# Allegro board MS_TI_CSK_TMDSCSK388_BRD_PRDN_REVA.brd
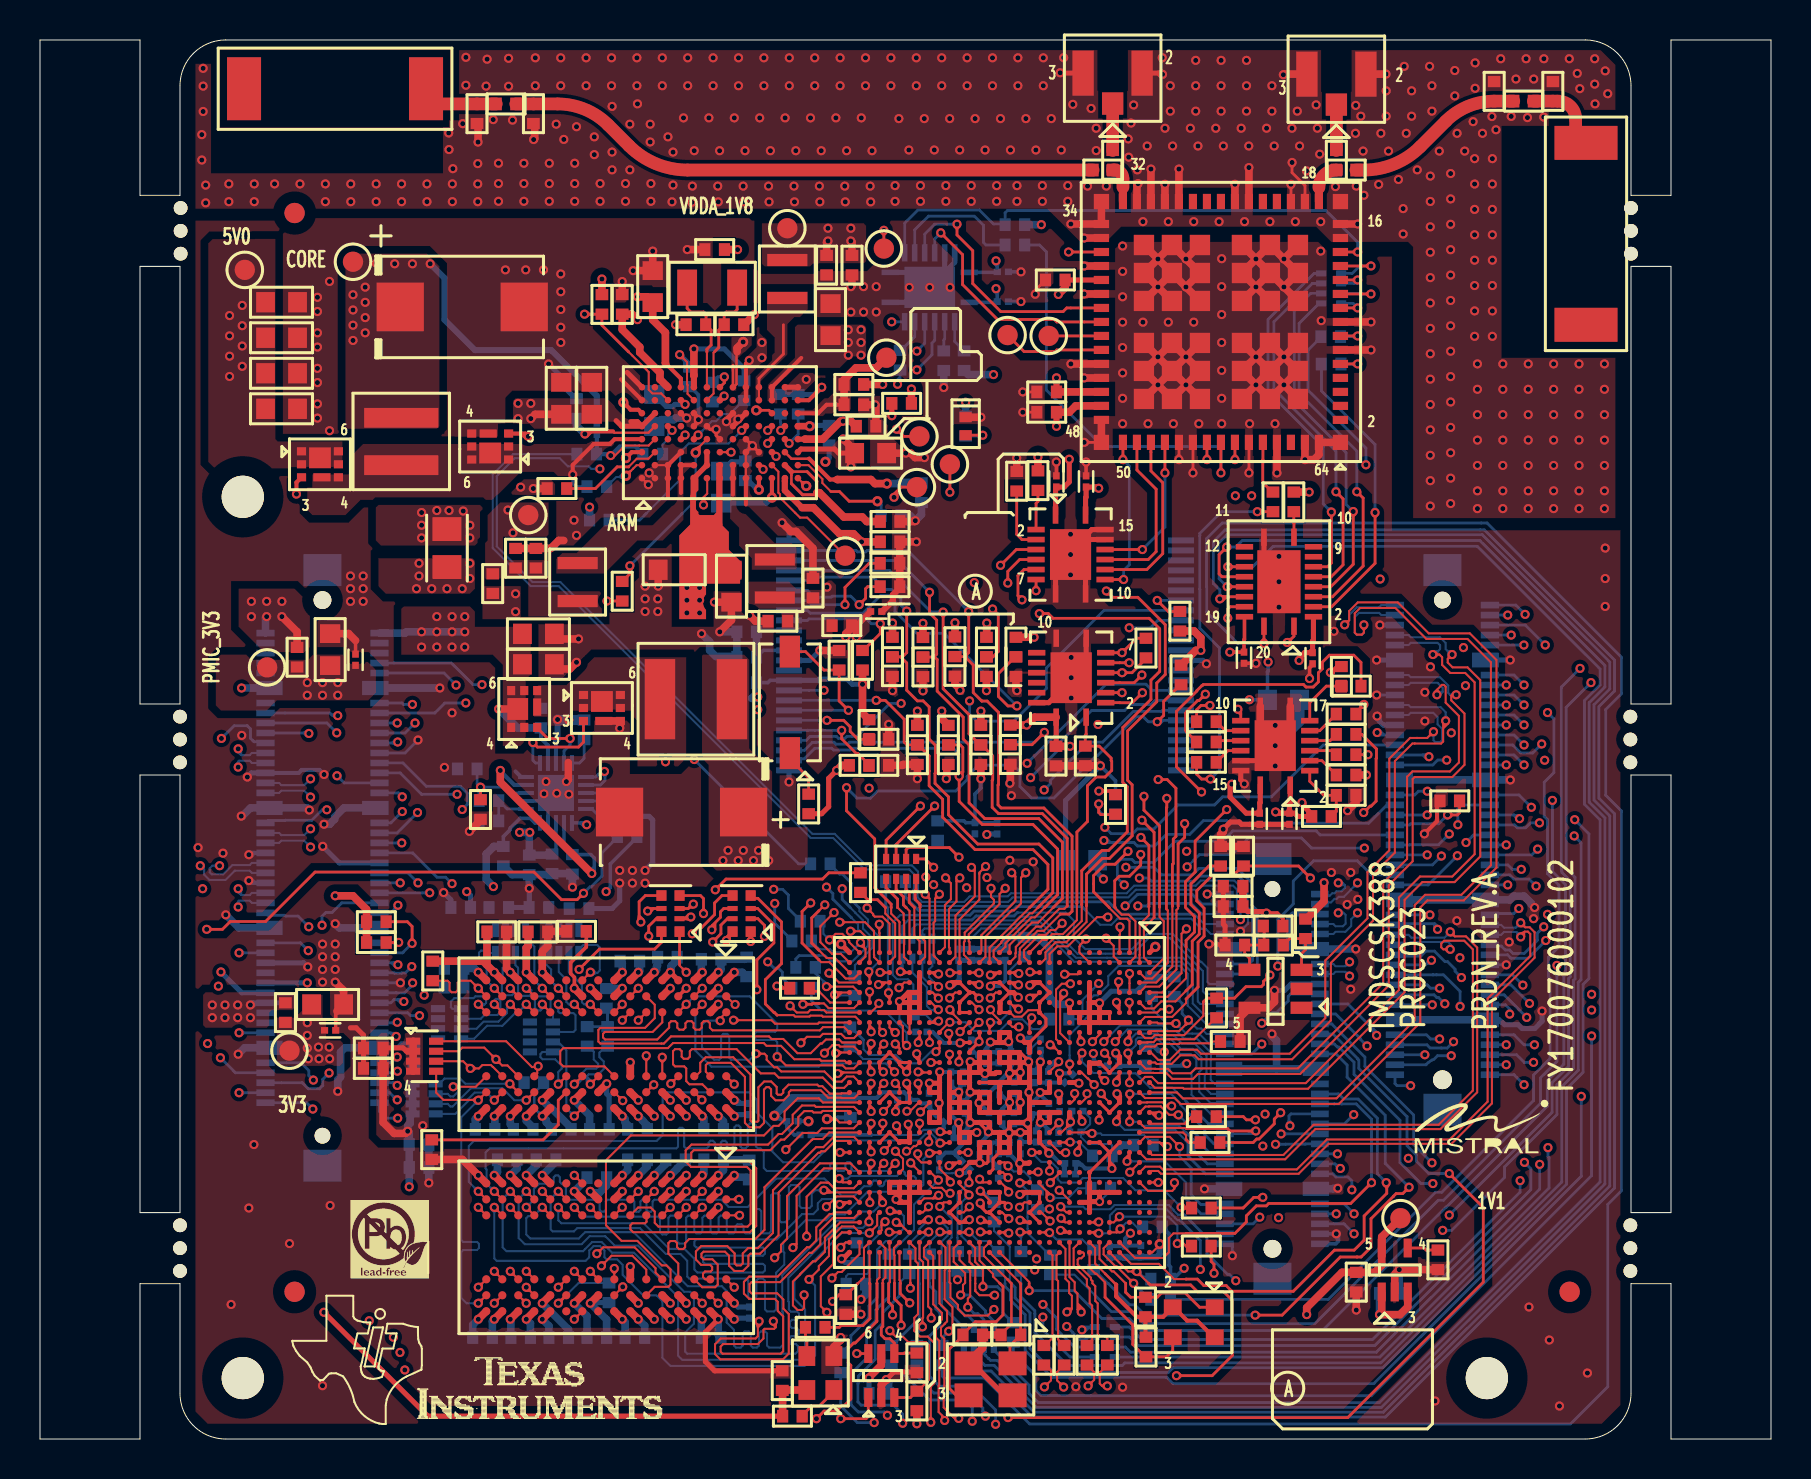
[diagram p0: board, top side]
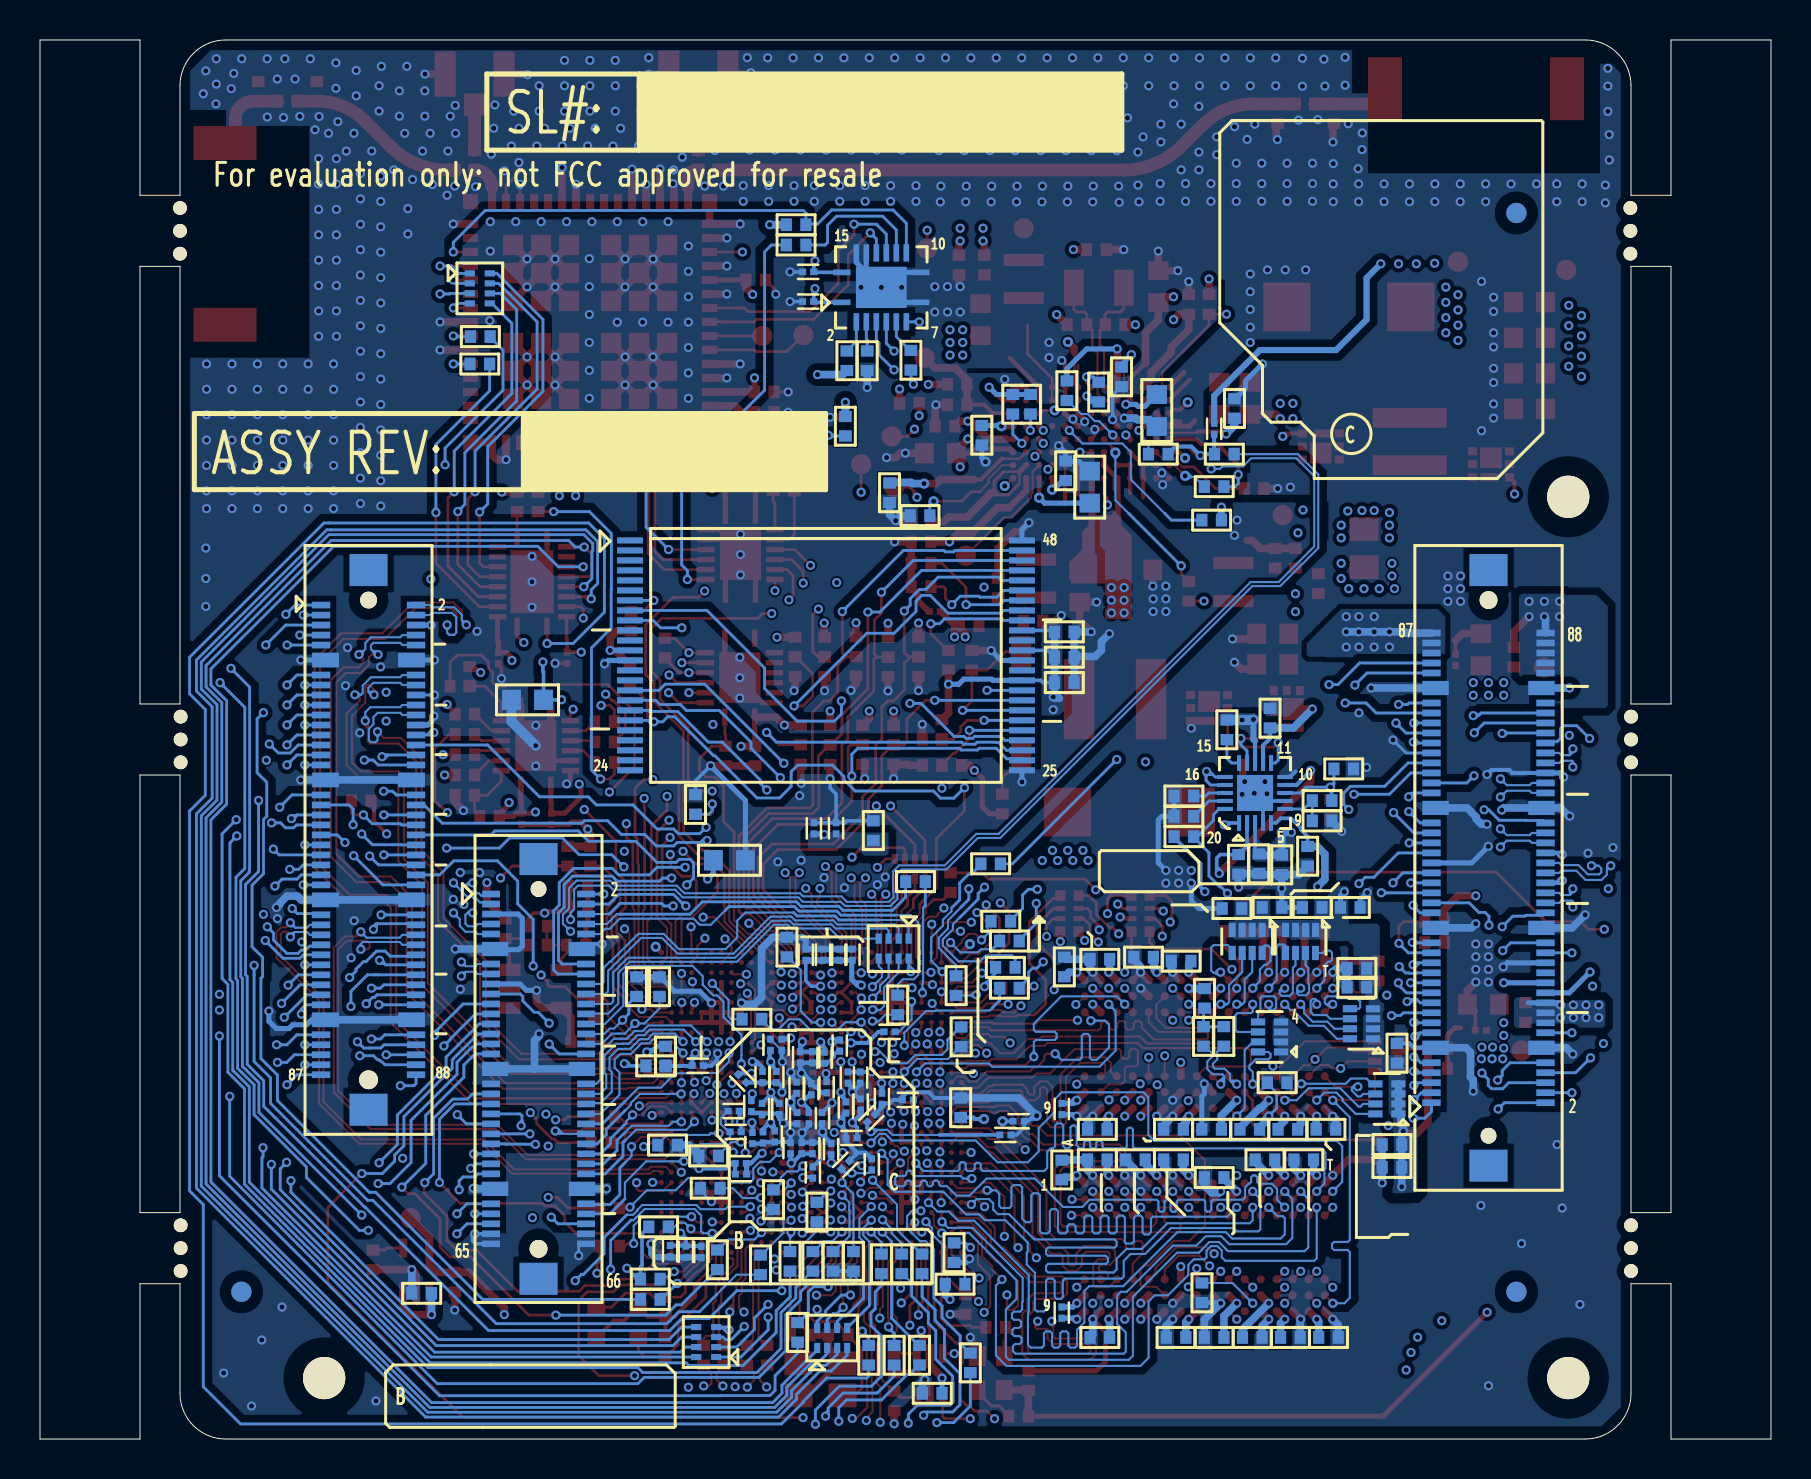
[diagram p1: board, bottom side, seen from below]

Outline 86.55 x 70 mm; copper layers: TOP, L02_GND1, L03_SIG1, L04_PWR1, L05_PWR2, L06_SIG2, L07_GND2, BOTTOM. Coordinates in mm from the lower left corner of the outline.
Outline path: 0,70 5,70 5,62.23 7,62.23 7,67.71 arc(7.67,69.33) 9.29,70 77.27,70 arc(78.88,69.33) 79.55,67.71 79.55,62.23 81.55,62.23 81.55,70 86.55,70 86.55,0 81.55,0 81.55,7.77 79.55,7.77 79.55,2.29 arc(78.88,0.67) 77.27,0 9.29,0 arc(7.67,0.67) 7,2.29 7,7.77 5,7.77 5,0 0,0 0,70 ; 5,58.67 5,36.78 7,36.78 7,58.67 5,58.67 ; 5,33.22 7,33.22 7,11.33 5,11.33 5,33.22 ; 79.55,58.67 79.55,36.78 81.55,36.78 81.55,58.67 79.55,58.67 ; 79.55,33.22 81.55,33.22 81.55,11.33 79.55,11.33 79.55,33.22

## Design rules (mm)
net group DM388_CAM_PCLK: nets DM388_CAM_PCLK DM388_CAM_PCLK_UT_RTSN
net group DM388_GMII_RXD[0]: nets DM388_GMII_RXD[0] N14559434
net group DM388_GMII_RXD[5]: nets DM388_GMII_RXD[5] N14559309
net group DM388_GMII_RXD[6]: nets DM388_GMII_RXD[6] N14559366
net group DM388_GMII_RXD[7]: nets DM388_GMII_RXD[7] N14559352
net group DM388_GMII_TXD[0]: nets DM388_GMII_TXD[0] N11883885
net group DM388_GMII_TXD[1]: nets DM388_GMII_TXD[1] N11883897
net group DM388_GMII_TXD[2]: nets DM388_GMII_TXD[2] N11883909
net group DM388_GMII_TXD[3]: nets DM388_GMII_TXD[3] N11883921
net group DM388_GMII_TXD[4]: nets DM388_GMII_TXD[4] N11883933
net group DM388_GMII_TXD[5]: nets DM388_GMII_TXD[5] N11883945
net group DM388_GMII_TXD[6]: nets DM388_GMII_TXD[6] N11883957
net group DM388_GMII_TXD[7]: nets DM388_GMII_TXD[7] N11883969
net group DM388_GMII_TXEN: nets DM388_GMII_TXEN N14522146
net group DP1: nets N14600252 N14600256
net group DP2: nets N14600268 N14600316
net group HDMI-0: nets DM388_HDMI_DN0 DM388_HDMI_DP0
net group HDMI-1: nets DM388_HDMI_DN1 DM388_HDMI_DP1
net group HDMI-2: nets DM388_HDMI_DN2 DM388_HDMI_DP2
net group HDMI-CLK: nets DM388_HDMI_CLKN DM388_HDMI_CLKP
net group PCIE-RX: nets DM388_PCIE_RXN0 DM388_PCIE_RXP0
net group PCIE-TX: nets DM388_PCIE_TXN0 DM388_PCIE_TXP0
net group RF: nets N14575481 N14575485
net group SERDES_CLK: nets DM388_SERDES_CLKN DM388_SERDES_CLKP
net group USB: nets DM388_USB1_DM DM388_USB1_DP
net group USB0: nets DM388_USB0_DM DM388_USB0_DP
net group VREF_1.24V: nets N14595953 VREF_1.24V
net group BB_PMIC_3V3: nets BB_PMIC_3V3
net group CLK: nets CLK32OUT_PMIC DM388_GMII_GMTCLK DM388_GMII_RCLK DM388_MCASP0_ACLKR DM388_MCASP1_ACLKR DM388_WLAN_CLKOUT DM388_WLAN_CLKOUT1
net group CVDD_ARM: nets TPS_CVDD_ARM
net group CVDD_HDVICP: nets TPS_CVDD_HDVICP
net group DDR: nets DM388_DDR0_A0 DM388_DDR0_A1 DM388_DDR0_A2 DM388_DDR0_A3 DM388_DDR0_A4 DM388_DDR0_A5 DM388_DDR0_A6 DM388_DDR0_A7 DM388_DDR0_A8 DM388_DDR0_A9 DM388_DDR0_A10 DM388_DDR0_A11 DM388_DDR0_A12 DM388_DDR0_A13 DM388_DDR0_A14 DM388_DDR0_BA0 DM388_DDR0_BA1 DM388_DDR0_BA2 DM388_DDR0_CASN DM388_DDR0_CKE DM388_DDR0_CLK DM388_DDR0_CLKN DM388_DDR0_CS0N DM388_DDR0_DQ0 DM388_DDR0_DQ1 DM388_DDR0_DQ2 DM388_DDR0_DQ3 DM388_DDR0_DQ4 DM388_DDR0_DQ5 DM388_DDR0_DQ6 DM388_DDR0_DQ7 DM388_DDR0_DQ8 DM388_DDR0_DQ9 DM388_DDR0_DQ10 DM388_DDR0_DQ11 DM388_DDR0_DQ12 DM388_DDR0_DQ13 DM388_DDR0_DQ14 DM388_DDR0_DQ15 DM388_DDR0_DQ16 DM388_DDR0_DQ17 DM388_DDR0_DQ18 DM388_DDR0_DQ19 DM388_DDR0_DQ20 DM388_DDR0_DQ21 DM388_DDR0_DQ22 DM388_DDR0_DQ23 DM388_DDR0_DQ24 DM388_DDR0_DQ25 DM388_DDR0_DQ26 DM388_DDR0_DQ27 DM388_DDR0_DQ28 DM388_DDR0_DQ29 DM388_DDR0_DQ30 DM388_DDR0_DQ31 DM388_DDR0_DQM0 DM388_DDR0_DQM1 DM388_DDR0_DQM2 DM388_DDR0_DQM3 DM388_DDR0_DQS0 DM388_DDR0_DQS0N DM388_DDR0_DQS1 DM388_DDR0_DQS1N DM388_DDR0_DQS2 DM388_DDR0_DQS2N DM388_DDR0_DQS3 DM388_DDR0_DQS3N DM388_DDR0_ODT0 DM388_DDR0_RASN DM388_DDR0_RST DM388_DDR0_WEN
net group DM388_CSI: nets DM388_CSI_DX0 DM388_CSI_DX1 DM388_CSI_DX2 DM388_CSI_DX3 DM388_CSI_DX4 DM388_CSI_DY0 DM388_CSI_DY1 DM388_CSI_DY2 DM388_CSI_DY3 DM388_CSI_DY4
net group DM388_GMII_GMTCLK: nets N14522090
net group DM388_GMII_RCLK: nets N14719324
net group DM388_MCASP0_ACLKR: nets N14776712
net group DM388_MCASP1_ACLKR: nets N14776629
net group GMII: nets DM388_GMII_COL DM388_GMII_CRS DM388_GMII_MTCLK DM388_GMII_RXD[1] DM388_GMII_RXD[2] DM388_GMII_RXD[3] DM388_GMII_RXD[4] DM388_GMII_RXDV DM388_GMII_RXER DM388_I2C2_SCL DM388_I2C2_SDA DM388_MCA[1]_AHCLKX DM388_MCASP0_ACLKX DM388_MCASP0_AFSR DM388_MCASP0_AFSX DM388_MCASP0_AXR0 DM388_MCASP0_AXR1 DM388_MCASP0_AXR2 DM388_MCASP0_AXR3 DM388_MCASP0_AXR4 DM388_MCASP0_AXR5 DM388_MCASP1_ACLKX DM388_MCASP1_AFSR DM388_MCASP1_AFSX DM388_MCASP1_AXR0 DM388_MCASP1_AXR1 DM388_MDIO_CLK DM388_MDIO_DAT DM388_MMC0_CLK DM388_MMC0_CMD DM388_MMC0_DAT0 DM388_MMC0_DAT1 DM388_MMC0_DAT2 DM388_MMC0_DAT3 DM388_MMC1_CLK DM388_MMC1_CMD DM388_MMC1_DAT0 DM388_MMC1_DAT1 DM388_MMC1_DAT2 DM388_MMC1_DAT3 DM388_MMC1_DAT6/GP0_12 DM388_MMC1_DAT7/GP0_13 DM388_MMC1_SDCD DM388_MMC2_CMD DM388_MMC2_DAT0 DM388_MMC2_DAT1 DM388_MMC2_DAT2 DM388_MMC2_DAT3 DM388_MMC2_DAT4 DM388_MMC2_DAT5 DM388_MMC2_DAT6 DM388_MMC2_DAT7 DM388_MMC2_DAT_0 DM388_MMC2_DAT_1 DM388_MMC2_DAT_3 DM388_MMC2_DAT_4 DM388_MMC2_DAT_5 DM388_MMC2_DAT_6 DM388_MMC2_DAT_7 DM388_MMC2_S_CLK DM388_MMC2_SCLK DM388_MUX_SEL NRESPWRON2
net group OTHERS: nets BB_VCC3V3 CC_RST CLKIN32 CORE_CVDD DDR_PGOOD DM388_BT_EN DM388_BTMODE[0] DM388_BTMODE[1] DM388_BTMODE[2] DM388_BTMODE[3] DM388_BTMODE[4] DM388_BTMODE[5] DM388_BTMODE[6] DM388_BTMODE[7] DM388_BTMODE[8] DM388_BTMODE[9] DM388_BTMODE[10] DM388_BTMODE[11] DM388_BTMODE[12] DM388_BTMODE[13] DM388_BTMODE[14] DM388_BTMODE[15] DM388_CAM_DAT0 DM388_CAM_DAT1 DM388_CAM_DAT2 DM388_CAM_DAT3 DM388_CAM_DAT4 DM388_CAM_DAT5 DM388_CAM_DAT6 DM388_CAM_DAT7 DM388_CAM_DAT8 DM388_CAM_DAT9 DM388_CAM_DAT10 DM388_CAM_DAT11 DM388_CAM_DAT12 DM388_CAM_DAT13 DM388_CAM_DAT14 DM388_CAM_DAT15 DM388_CAM_FLD DM388_CAM_FLD_UT_CTSN DM388_CAM_HS DM388_CAM_RESET DM388_CAM_SHUTTER DM388_CAM_STROBE DM388_CAM_VS DM388_CAM_WEN DM388_DDR0_VTP DM388_EMU0 DM388_EMU1 DM388_GP0[9] DM388_GP1[10] DM388_GP1[14] DM388_GP1[24] DM388_GP1[25] DM388_GP1[30] DM388_GP3[3] DM388_GP3[4] DM388_GPMC_ALE DM388_GPMC_CLE DM388_GPMC_CS[0]N DM388_GPMC_OEN_REN DM388_GPMC_WAIT0 DM388_GPMC_WEN DM388_GPMC_WPN DM388_HDMI_CEC DM388_HDMI_HPDET DM388_HDMI_SCL DM388_HDMI_SDA DM388_I2C0_SCL DM388_I2C0_SDA DM388_PMIC_PWRON DM388_PORN DM388_RSTOUT DM388_RTCK DM388_SPI0_SCS[0]N DM388_SPI1_D[0] DM388_SPI1_D[1] DM388_SPI1_SCLK DM388_SPI1_SCS[0]N DM388_SPI[0]_D[0] DM388_SPI[0]_D[1] DM388_SPI[0]_SCLK DM388_TCLK DM388_TDI DM388_TDO DM388_TMS DM388_TPS_SLEEP DM388_TRSTN DM388_UART0_CTSN DM388_UART0_RTSN DM388_UART0_RXD DM388_UART0_TXD DM388_UART1_RXD DM388_UART1_TXD DM388_UART2_CTSN DM388_UART2_RTSN DM388_UART2_RXD DM388_UART2_TXD DM388_USB0_CE DM388_USB0_DRVVBUS DM388_USB0_ID DM388_USB0_VBUSIN DM388_USB1_CE DM388_USB1_DRVVBUS DM388_USB1_ID DM388_USB1_VBUSIN DM388_VIN[0]A_CLK DM388_VIN[0]A_D[0] DM388_VIN[0]A_D[1] DM388_VIN[0]A_D[2] DM388_VIN[0]A_D[3] DM388_VIN[0]A_D[4] DM388_VIN[0]A_D[5] DM388_VIN[0]A_D[6] DM388_VIN[0]A_D[7] DM388_VIN[0]A_D[8]_BD[0] DM388_VIN[0]A_D[9]_BD[1] DM388_VIN[0]A_D[10]_BD[2] DM388_VIN[0]A_D[12]_BD[4] DM388_VIN[0]A_DE DM388_VIN[0]A_FLD DM388_VIN[0]A_HSYNC DM388_VIN[0]A_VSYNC DM388_VIN[0]B_CLK DM388_WARM_RSTN DM388_WLAN_EN DM388_WLAN_IRQ EN_LS_3V3 EN_TPS51216 ENET_RSTN HDDAC_A HDDAC_B HDDAC_C HDDAC_HSYNC HDDAC_VREF HDDAC_VSYNC N11812612 N11838777 N11838793 N11838802 N11838814 N11846918 N11847334 N11848351 N11848810 N12895522 N12895682 N12895686 N12909578 N12909638 N12910002 N12911225 N12911351 N12969077 N12971691 N12971710 N12972021 N12972241 N12972253 N12973009 N12973023 N12985066 N12985136 N12993482 N14066974 N14067031 N14067125 N14068093 N14068298 N14068467 N14068656 N14068754 N14086942 N14162633 N14387261 N14387269 N14434808 N14434812 N14445231 N14486422 N14519770 N14553661 N14554807 N14554839 N14564270 N14564274 N14564278 N14564302 N14564360 N14565290 N14565662 N14567220 N14567296 N14568444 N14568464 N14568476 N14572177 N14572181 N14599932 N14599936 N14600104 N14600424 N14600444 N14634458 N14645029 N14648093 N14719275 N14776785 N14776789 N14783196 N14783200 N14783204 N14783208 N15102842 N15102865 N15102869 N15102988 N15110091 N15110100 N15110106 N15110404 N15110444 N15123588 N15123674 N15123798 N15123807 N15123817 N15123828 N15124532 N15124704 N15124708 N15124784 N15124788 N15124799 N15124807 N15124875 N15140205 N15266407 N15454827 OSC_WAKE PLL_1V8 REFGND TPS_CORE_CVDD TPS_GPIO_3V3 TPS_HDMI_CSI_1V8 TPS_INT1 TPS_LDO5_3V3 TPS_LDO6_3V3 TPS_USB_1V8 TPS_USB_3V3 TPS_VDAC_1V8 TPS_VDDA_1V8 TPS_VHD_1V1 TV_OUT0 VBACKUP VCC_3V3 VCC_5V0 VCC_CAM VDAC_1V8 VDD_DDR VDD_DDR_VREF VDDR_VTT VRTC WL_DM388_BT_EN WL_DM388_MCASP0_ACLKX WL_DM388_MCASP0_AFSX WL_DM388_MCASP0_AXR0 WL_DM388_MCASP0_AXR1 WL_DM388_MMC0_CLK WL_DM388_MMC0_CMD WL_DM388_MMC0_DAT0 WL_DM388_MMC0_DAT1 WL_DM388_MMC0_DAT2 WL_DM388_MMC0_DAT3 WL_DM388_UART2_CTSN WL_DM388_UART2_RTSN WL_DM388_UART2_RXD WL_DM388_UART2_TXD WL_DM388_WLAN_CLKOUT WL_DM388_WLAN_EN WL_DM388_WLAN_IRQ XTAL_GND1 XTAL_GND2
net group RF_ANT1: nets N14575533 N15013442 RF_ANT1
net group RF_ANT2: nets N14575591 N15014410 RF_ANT2

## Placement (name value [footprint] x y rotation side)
A1  W3006  [ANT2_W3006_390X130_SMD]  14.75 67.56 180 top
A2  W3006  [ANT2_W3006_390X130_SMD]  77.3 60.3 270 top
C1  2.4pF  [CAP0402]  74.18 66.94 0 top
C2  1pF  [CAP0402]  23.3 66.8 180 top
C3  10uF  [CAP0402]  39.33 58.73 270 top
C4  0.1uF  [CAP0402]  40.6 58.73 270 top
C5  0.1uF  [CAP0402]  50.77 57.99 180 top
C6  4.7uF  [CAP0603]  30.64 57.66 90 top
C7  10uF  [CAP0603]  12.08 56.88 0 top
C8  2.2uF  [CAP0402]  29.11 56.77 90 top
C9  10uF  [CAP0603]  39.53 56.01 90 top
C10  22pF  [CAP0402]  32.8 55.75 0 top
C11  22pF  [CAP0402]  34.7 55.75 180 top
C12  150uF_6.3V  [CAPT7343X]  21.11 56.64 0 top
C13  10uF  [CAP0603]  12.08 55.1 0 top
C14  10uF  [CAP0603]  12.08 53.32 0 top
C15  0.1uF  [CAP0402]  50.34 52.39 180 top
C16  4.7uF  [CAP0603]  26.06 52.07 90 top
C17  1uF  [CAP0603]  27.59 52.07 90 top
C18  2.2uF  [CAP0402]  40.69 51.75 0 top
C19  10uF  [CAP0603]  12.08 51.54 0 top
C20  0.1uF  [CAP0402]  50.34 51.37 180 top
C21  2.2uF  [CAP0402]  41.3 50.67 0 top
C22  4.7uF  [CAP0603]  41.53 49.33 0 top
C23  0.1uF  [CAP0201]  50.82 47.91 90 top
C24  0.1uF  [CAP0201]  52.3 47.91 90 top
C25  10uF  [CAP0402]  23.78 44.07 90 top
C26  2.2uF  [CAP0402]  42.51 45.91 0 top
C27  10uF  [CAP0402]  38.65 42.58 90 top
C28  0.1uF  [CAP0402]  24.79 44.07 90 top
C29  2.2uF  [CAP0402]  42.51 44.89 0 top
C30  0.1uF  [CAP0402]  36.89 40.92 180 top
C31  10uF  [CAP0603]  31.71 43.49 180 top
C32  10uF  [CAP0603]  34.57 42.67 270 top
C33  10uF  [CAP0603]  24.92 40.29 0 top
C34  10uF  [CAP0603]  14.51 39.5 90 top
C35  0.1uF  [CAP0201]  60.2 39.09 270 top
C36  0.1uF  [CAP0201]  63.63 39.07 270 top
C37  0.1uF  [CAP0201]  15.78 38.99 90 top
C38  10uF  [CAP0603]  24.92 38.76 0 top
C39  0.1uF  [CAP0201]  41.81 41.4 180 top
C40  0.1uF  [CAP0402]  50.8 34.17 270 top
C41  0.01uF  [CAP0201]  44.96 13.74 90 bottom
C42  1uF  [CAP0402]  25.05 36.07 90 bottom
C43  68uF_20V  [CAPT7343D]  32.08 31.37 180 top
C44  0.1uF  [CAP0201]  60.99 31.03 270 top
C45  0.1uF  [CAP0201]  62.47 31.03 270 top
C46  0.1uF  [CAP0402]  59.66 27.66 0 top
C47  0.1uF  [CAP0402]  18.7 19.3 270 bottom
C48  0.1uF  [CAP0402]  26.95 26.54 180 bottom
C49  0.1uF  [CAP0402]  16.67 18.54 0 top
C50  0.1uF  [CAP0402]  16.67 19.56 0 top
C51  0.01uF  [CAP0402]  26.83 25.4 180 top
C52  0.1uF  [CAP0402]  24.9 25.38 0 top
C53  0.01uF  [CAP0402]  22.84 25.38 0 top
C54  1uF  [CAP0402]  59.74 24.72 180 top
C55  10uF  [CAP0603]  14.38 21.74 0 top
C56  0.1uF  [CAP0201]  14.51 20.45 0 top
C57  1nF  [CAP0402]  69.9 8.97 270 top
C58  1uF  [CAP0402]  65.82 7.85 270 top
C59  18pF  [CAP0402]  55.27 6.6 90 top
C60  33pF  [CAP0402]  48.54 5.21 0 top
C61  33pF  [CAP0402]  46.64 5.21 0 top
C62  18pF  [CAP0402]  55.3 4.6 270 top
C63  0.1uF  [CAP0402]  50.19 4.19 270 top
C64  0.1uF  [CAP0402]  51.21 4.19 270 top
C65  270pF  [CAP0402]  52.35 4.19 270 top
C66  270pF  [CAP0402]  53.37 4.19 270 top
C67  0.1uF  [CAP0402]  37.11 2.92 90 top
C68  0.1uF  [CAP0201]  48.14 58.4 0 bottom
C69  0.1uF  [CAP0201]  48.14 56.91 0 bottom
C70  2.2uF  [CAP0402]  32.47 53.14 270 bottom
C71  0.1uF  [CAP0402]  33.62 52.38 90 bottom
C72  2.2uF  [CAP0603]  30.71 51.46 270 bottom
C73  2.2uF  [CAP0402]  26.83 51.56 90 bottom
C74  4.7uF  [CAP0402]  39.46 50.22 270 bottom
C75  330pF  [CAP0402]  30.64 49.28 180 bottom
C76  2.2uF  [CAP0402]  35.27 48.45 90 bottom
C77  0.1uF  [CAP0402]  27.84 47.65 180 bottom
C78  4.7uF  [CAP0603]  34.07 47.63 90 bottom
C79  2.2uF  [CAP0402]  44.07 47.35 270 bottom
C80  .01uF  [CAP0402]  35.34 40.39 180 bottom
C81  0.1uF  [CAP0402]  35.34 39.12 180 bottom
C82  1uF  [CAP0402]  35.34 37.85 180 bottom
C83  10uF  [CAP0603]  62.17 36.98 0 bottom
C84  0.1uF  [CAP0402]  27.21 35.48 90 bottom
C85  0.01uF  [CAP0402]  21.37 33.53 180 bottom
C86  0.1uF  [CAP0402]  22.45 30.93 0 bottom
C87  0.01uF  [CAP0201]  46.75 30.56 90 bottom
C88  0.1uF  [CAP0201]  47.86 30.55 90 bottom
C89  10uF  [CAP0402]  44.88 30.44 90 bottom
C90  0.22uF  [CAP0402]  23.17 29.16 270 bottom
C91  10uF  [CAP0603]  52.08 28.96 180 bottom
C92  10uF  [CAP0402]  25.61 28.78 270 bottom
C93  10uF  [CAP0402]  26.62 28.75 270 bottom
C94  10uF  [CAP0402]  24.46 28.73 270 bottom
C95  0.1uF  [CAP0402]  24.95 26.59 0 bottom
C96  0.1uF  [CAP0402]  22.94 26.59 180 bottom
C97  0.1uF  [CAP0402]  21.04 26.59 0 bottom
C98  0.1uF  [CAP0402]  28.32 22.05 270 bottom
C99  1uF  [CAP0402]  49.2 24.61 270 bottom
C100  0.1uF  [CAP0201]  48.26 24.23 90 bottom
C101  0.01uF  [CAP0201]  47.4 24.23 90 bottom
C102  0.01uF  [CAP0201]  46.59 24.23 90 bottom
C103  0.01uF  [CAP0201]  45.93 24.23 90 bottom
C104  0.01uF  [CAP0402]  31.37 24.11 0 bottom
C105  0.01uF  [CAP0402]  33.56 24 0 bottom
C106  0.1uF  [CAP0402]  29.49 23.91 0 bottom
C107  0.1uF  [CAP0402]  35.34 23.62 90 bottom
C108  0.1uF  [CAP0402]  20.7 23.55 180 bottom
C109  0.1uF  [CAP0402]  20.7 22.61 180 bottom
C110  0.1uF  [CAP0201]  44.07 20.37 0 bottom
C111  1uF  [CAP0402]  40.49 20.12 90 bottom
C112  0.1uF  [CAP0402]  24.69 17.83 180 bottom
C113  0.01uF  [CAP0201]  50.03 19.73 90 bottom
C114  0.01uF  [CAP0201]  49.47 19.73 270 bottom
C115  0.01uF  [CAP0201]  48.54 19.1 270 bottom
C116  0.01uF  [CAP0201]  47.93 19.1 270 bottom
C117  0.01uF  [CAP0201]  47.32 19.08 270 bottom
C118  0.01uF  [CAP0201]  53.66 18.68 180 bottom
C119  0.01uF  [CAP0201]  50.42 18.11 270 bottom
C120  0.01uF  [CAP0201]  49.74 18.11 270 bottom
C121  0.1uF  [CAP0201]  46.16 18.09 90 bottom
C122  0.01uF  [CAP0201]  45.55 18.09 270 bottom
C123  0.01uF  [CAP0201]  51.44 18.03 225 bottom
C124  0.01uF  [CAP0201]  47.22 17.6 270 bottom
C125  0.01uF  [CAP0201]  48.72 17.58 90 bottom
C126  0.01uF  [CAP0201]  47.98 17.5 90 bottom
C127  0.01uF  [CAP0201]  44.45 17.02 270 bottom
C128  0.1uF  [CAP0201]  43.16 16.97 180 bottom
C129  0.01uF  [CAP0201]  45.52 16.74 90 bottom
C130  0.1uF  [CAP0201]  50.98 16.66 270 bottom
C131  0.1uF  [CAP0201]  46.26 16.59 270 bottom
C132  0.1uF  [CAP0402]  40.52 16.58 270 bottom
C133  0.1uF  [CAP0201]  50.45 16.51 90 bottom
C134  0.1uF  [CAP0201]  49.58 16.51 90 bottom
C135  0.01uF  [CAP0201]  35.46 16.51 270 bottom
C136  0.1uF  [CAP0201]  51.87 16.41 180 bottom
C137  0.01uF  [CAP0201]  48.7 16.05 270 bottom
C138  0.01uF  [CAP0201]  48.11 16.05 270 bottom
C139  0.1uF  [CAP0201]  44.99 16.05 315 bottom
C140  0.01uF  [CAP0201]  47.45 16.05 270 bottom
C141  0.01uF  [CAP0201]  37.62 15.9 180 bottom
C142  0.1uF  [CAP0402]  26.06 15.49 180 bottom
C143  0.01uF  [CAP0402]  33.68 15.49 0 bottom
C144  0.01uF  [CAP0402]  29.87 15.49 0 bottom
C145  0.1uF  [CAP0402]  27.97 15.49 0 bottom
C146  0.01uF  [CAP0402]  24.16 15.49 180 bottom
C147  0.01uF  [CAP0402]  22.25 15.49 180 bottom
C148  0.01uF  [CAP0201]  51.77 15.37 0 bottom
C149  0.1uF  [CAP0201]  38.28 15.22 0 bottom
C150  0.1uF  [CAP0201]  49.81 15.14 90 bottom
C151  0.01uF  [CAP0201]  50.4 15.09 270 bottom
C152  0.01uF  [CAP0201]  50.93 15.06 270 bottom
C153  0.01uF  [CAP0201]  45.98 15.06 0 bottom
C154  0.1uF  [CAP0402]  18.95 14.73 180 bottom
C155  1uF  [CAP0402]  55.17 14.71 180 bottom
C156  0.1uF  [CAP0201]  48.47 14.56 90 bottom
C157  0.01uF  [CAP0201]  47.93 14.56 90 bottom
C158  0.01uF  [CAP0201]  46.99 14.5 90 bottom
C159  0.01uF  [CAP0201]  49.03 14.55 90 bottom
C160  0.1uF  [CAP0201]  46.56 19.69 90 bottom
C161  1uF  [CAP0402]  53.12 14.16 180 bottom
C162  0.01uF  [CAP0402]  33.68 13.97 0 bottom
C163  0.01uF  [CAP0402]  31.78 13.97 0 bottom
C164  0.1uF  [CAP0402]  29.87 13.97 0 bottom
C165  0.1uF  [CAP0402]  25.3 13.97 0 bottom
C166  0.01uF  [CAP0402]  23.36 13.97 0 bottom
C167  0.1uF  [CAP0201]  51.52 13.79 180 bottom
C168  0.01uF  [CAP0201]  46.28 13.72 135 bottom
C169  0.1uF  [CAP0402]  18.95 13.59 180 bottom
C170  0.1uF  [CAP0402]  35.46 13.46 90 bottom
C171  0.01uF  [CAP0201]  47.91 13.34 90 bottom
C172  0.01uF  [CAP0201]  51.5 13.25 0 bottom
C173  0.01uF  [CAP0402]  27.84 13.08 0 bottom
C174  1uF  [CAP0402]  53.04 12.55 180 bottom
C175  1uF  [CAP0402]  49.88 11.97 90 bottom
C176  0.1uF  [CAP0201]  55.05 9.4 270 bottom
C177  0.01uF  [CAP0201]  54.26 9.37 270 bottom
C178  0.01uF  [CAP0201]  53.48 9.36 270 bottom
C179  1uF  [CAP0402]  46.89 8.89 90 bottom
C180  1uF  [CAP0402]  45.88 8.89 270 bottom
C181  1uF  [CAP0402]  67.47 7.29 0 bottom
C182  0.01uF  [CAP0201]  35.46 6.33 270 bottom
C183  0.01uF  [CAP0402]  33.56 5.08 0 bottom
C184  0.01uF  [CAP0402]  29.75 5.08 0 bottom
C185  0.1uF  [CAP0402]  27.84 5.08 0 bottom
C186  0.1uF  [CAP0402]  25.94 5.08 180 bottom
C187  0.01uF  [CAP0402]  24.03 5.08 180 bottom
C188  0.01uF  [CAP0402]  22.13 5.08 180 bottom
C189  0.1uF  [CAP0402]  41.94 2.29 0 bottom
C190  0.1uF  [CAP0201]  27.84 50.55 270 bottom
D1  TLV431ACDBVR  [SOT23-5]  61.78 22.53 180 top
J1  CON_3_U.FL-R-SMT  [CON_3X1_U-FL-R-SMT_S_S_S]  53.63 68.34 270 top
J2  CON_3_U.FL-R-SMT  [CON_3X1_U-FL-R-SMT_S_S_S]  64.82 68.29 270 top
J3  CON_PMC_40X2_M  [CON_PMC40X2_FX11LA-80P_P_S_S]  70.12 29.98 270 bottom
J4  CON_PMC_2X40_F  [CON_PMC40X2_FX11LA-80S_S_S_S]  14.12 28.58 90 bottom
J5  CON_PMC_30X2_M  [CON_PMC30X2_FX11LA-60P_P_S_S]  61.62 18.52 270 bottom
L1  2.2nH  [IND0402]  72.71 67.43 90 top
L2  1.8nH  [IND0402]  75.65 67.43 90 top
L3  1.3nH  [IND0402]  21.85 66.31 270 top
L4  2.2uH  [IND_VLS252012HBX_110X90_SMD]  37.37 58.04 90 top
L5  1.5uH  [IND_XAL4030_170X170_SMD]  18.06 49.91 90 top
L6  2.2uH  [IND_VLS252012HBX_110X90_SMD]  26.88 42.88 270 top
L7  2.2uH  [IND_VLS252012HBX_110X90_SMD]  36.74 43.05 270 top
L8  3.3uH  [IND_NRS5020_200X200_SMD]  32.8 37.02 270 top
LD1  SML-P11MTT86  [LED_0402]  46.28 50.67 180 top
MOD1  WL1837MODGIMOCT  [MOD100_WL1831M_530X530]  59.05 55.89 180 top
NOREF  -  []  0 0 90 top
NOREF#2  -  []  5 0 0 top
NOREF#3  -  []  7.75 5.31 90 top
NOREF#4  -  []  72.34 3.05 0 top
NOREF#5  -  [unnamed#2]  7 10.69 270 top
NOREF#6  -  [unnamed#2]  79.52 8.41 90 top
NOREF#7  -  []  0 70 0 top
NOREF#8  -  []  7 67.71 0 top
NOREF#9  -  [unnamed#3]  10.14 47.14 0 top
NOREF#10  -  []  81.55 0 0 top
NOREF#11  -  []  7 2.29 0 top
NOREF#12  -  []  7.01 -34.92 0 top
NOREF#13  -  []  24.48 75.82 0 top
NOREF#14  -  []  9.27 0 90 top
NOREF#15  -  [unnamed#3]  76.48 7.37 0 top
NOREF#16  -  []  81.55 70 0 top
NOREF#17  -  [unnamed#2]  7 36.14 270 top
NOREF#18  -  [unnamed#3]  12.73 7.37 0 top
NOREF#19  -  [unnamed#2]  79.52 33.86 90 top
NOREF#20  -  [unnamed#3]  10.14 3.05 0 top
NOREF#21  -  [unnamed#2]  7.03 61.59 270 top
NOREF#22  -  [unnamed#3]  12.73 61.34 0 top
NOREF#23  -  []  72.06 15.34 0 top
NOREF#24  -  []  78.89 69.32 0 top
NOREF#25  -  []  -339.19 -104.45 0 top
NOREF#26  -  []  10.14 47.14 90 top
NOREF#27  -  [unnamed#2]  79.55 59.31 90 top
NOREF#28  -  [unnamed#3]  72.34 3.05 0 top
NOREF#29  -  []  -88.87 -4.44 0 top
NOREF#30  -  [unnamed#3]  76.48 7.37 180 bottom
NOREF#31  -  [unnamed#3]  12.73 7.37 180 bottom
NOREF#32  -  [unnamed#3]  12.73 61.34 180 bottom
Q1  CSD17313Q2  [SON6_CSD17313Q2_80X80]  22.51 49.66 90 top
Q2  CSD17313Q2  [SON6_CSD17313Q2_80X80]  14 48.77 270 top
Q3  CSD17313Q2  [SON6_CSD17313Q2_80X80]  28.1 36.58 270 top
Q4  CSD17313Q2  [SON6_CSD17313Q2_80X80]  24.21 36.53 0 top
R1  0E  [RES0402]  24.67 66.31 90 top
R2  0E  [RES0402]  53.63 63.98 90 top
R3  0E  [RES0402]  64.82 63.98 90 top
R4  0E  [RES0402]  53.14 63.49 180 top
R5  0E  [RES0402]  65.31 63.49 0 top
R6  0E  [RES0402]  33.74 59.51 0 top
R7  10K  [RES0402]  28.1 56.77 270 top
R8  0E  [RES0402]  40.69 52.76 0 top
R9  10K  [RES0402]  43.08 51.82 180 top
R10  10K  [RES0402]  49.9 47.95 270 top
R11  10K  [RES0402]  48.84 47.92 90 top
R12  100K  [RES0402]  25.85 47.56 180 top
R13  22E_1%  [RES0402]  61.65 46.89 90 top
R14  10K  [RES0402]  62.69 46.89 270 top
R15  0E  [RES0805]  20.35 44.58 270 top
R16  10K  [RES0402]  42.5 43.82 0 top
R17  0E  [RES0402]  22.64 42.8 270 top
R18  10K  [RES0402]  42.5 42.65 0 top
R19  22E_1%  [RES0402]  29.11 42.42 270 top
R20  10K  [RES0402]  57 40.92 90 top
R21  0E  [RES0402]  40.09 40.7 0 top
R22  10K  [RES0402]  45.75 39.64 270 top
R23  10K  [RES0402]  42.63 39.62 270 top
R24  10K  [RES0402]  47.32 39.62 270 top
R25  10K  [RES0402]  48.8 39.62 270 top
R26  10K  [RES0402]  44.15 39.61 270 top
R27  0E  [RES0402]  12.86 39.12 90 top
R28  100K  [RES0402]  39.96 38.96 90 top
R29  10K  [RES0402]  41.13 38.96 90 top
R30  10K  [RES0402]  45.75 38.66 270 top
R31  10K  [RES0402]  42.63 38.64 270 top
R32  10K  [RES0402]  47.32 38.64 270 top
R33  10K  [RES0402]  48.8 38.64 270 top
R34  10K  [RES0402]  44.15 38.63 270 top
R35  10K  [RES0402]  57.05 38.23 270 top
R36  0E  [RES0402]  65.07 38.16 270 top
R37  0E  [RES0402]  65.56 37.67 180 top
R38  22E_1%  [RES0402]  65.31 36.27 180 top
R39  22E_1%  [RES0402]  58.32 35.89 180 top
R40  10K  [RES0402]  41.46 35.5 270 top
R41  22E_1%  [RES0402]  65.31 35.26 180 top
R42  10K  [RES0402]  48.52 35.23 270 top
R43  10K  [RES0402]  43.87 35.22 270 top
R44  10K  [RES0402]  45.42 35.22 270 top
R45  10K  [RES0402]  47.04 35.22 270 top
R46  10K  [RES0402]  41.95 35.01 0 top
R47  22E_1%  [RES0402]  58.32 34.88 180 top
R48  10K  [RES0402]  48.52 34.25 270 top
R49  10K  [RES0402]  43.87 34.24 270 top
R50  10K  [RES0402]  45.42 34.24 270 top
R51  10K  [RES0402]  47.04 34.24 270 top
R52  22E_1%  [RES0402]  65.31 34.24 180 top
R53  10K  [RES0402]  52.27 34.18 270 top
R54  22E_1%  [RES0402]  58.32 33.86 180 top
R55  10K  [RES0402]  40.96 33.71 0 top
R56  10K  [RES0402]  41.94 33.71 0 top
R57  10K  [RES0402]  65.31 33.22 180 top
R58  10K  [RES0402]  65.31 32.21 0 top
R59  10K  [RES0402]  38.43 31.78 90 top
R60  10K  [RES0402]  53.78 31.75 270 top
R61  48.7K_1%  [RES0402]  22.03 31.5 270 top
R62  10K  [RES0402]  64.07 31.15 0 top
R63  2.67K_1%  [RES0402]  59.03 29.16 90 top
R64  165E_1%  [RES0402]  60.18 29.16 270 top
R65  22E_1%  [RES0402]  41.02 27.84 270 top
R66  4.99K_1%  [RES0402]  59.66 26.64 0 top
R67  10K  [RES0402]  16.82 25.88 0 top
R68  7.5K_1%  [RES0402]  61.66 25.67 0 top
R69  1K  [RES0402]  63.28 25.53 270 top
R70  10K  [RES0402]  16.82 24.84 0 top
R71  0E  [RES0402]  61.68 24.72 0 top
R72  10K  [RES0402]  19.64 23.42 270 top
R73  22E_1%  [RES0402]  37.98 22.56 0 top
R74  2.7K_1%  [RES0402]  58.83 21.57 270 top
R75  0E  [RES0402]  12.27 21.34 90 top
R76  4.7K_1%  [RES0402]  59.52 19.89 180 top
R77  22E_1%  [RES0402]  58.32 16.13 0 top
R78  22E_1%  [RES0402]  58.5 14.83 0 top
R79  22E_1%  [RES0402]  58.07 11.56 180 top
R80  22E_1%  [RES0402]  58.07 9.65 180 top
R81  10K  [RES0402]  40.29 6.73 270 top
R82  22E_1%  [RES0402]  38.76 5.59 0 top
R83  10K  [RES0402]  43.84 3.81 270 top
R84  10K  [RES0402]  43.84 1.91 90 top
R85  10K  [RES0402]  37.62 1.14 0 top
R86  10K  [RES0402]  48.75 60.76 180 bottom
R87  22E_1%  [RES0402]  48.75 59.74 0 bottom
R88  1K  [RES0402]  46.28 50.67 270 bottom
R89  22E_1%  [RES0402]  64.53 55.16 0 bottom
R90  22E_1%  [RES0402]  43.01 53.98 90 bottom
R91  10K  [RES0402]  46.21 53.95 90 bottom
R92  10K  [RES0402]  45.19 53.95 270 bottom
R93  22E_1%  [RES0402]  64.56 53.79 0 bottom
R94  10K  [RES0402]  35.21 52.45 270 bottom
R95  10K  [RES0402]  37.91 51.77 270 bottom
R96  10K  [RES0402]  37.02 51.77 270 bottom
R97  10K  [RES0402]  42.55 46.2 180 bottom
R98  10K  [RES0402]  27.97 45.97 0 bottom
R99  51K  [RES0402]  29.36 32.17 0 bottom
R100  10K_1%  [RES0402]  22.45 31.94 180 bottom
R101  10K  [RES0402]  53.78 31.75 90 bottom
R102  200K  [RES0402]  29.36 31.16 180 bottom
R103  10K  [RES0402]  29.36 30.14 180 bottom
R104  0E  [RES0402]  39.02 28.78 180 bottom
R105  22E_1%  [RES0402]  42.78 27.89 0 bottom
R106  22E_1%  [RES0402]  38.51 25.91 180 bottom
R107  49.9E_1%  [RES0402]  28.38 20.14 90 bottom
R108  49.9E_1%  [RES0402]  27.36 20.14 90 bottom
R109  0E  [RES0402]  38.08 24.92 180 bottom
R110  0E  [RES0402]  38.28 23.6 180 bottom
R111  0E  [RES0402]  40.75 22.68 90 bottom
R112  165E_1%  [RES0402]  56.72 22.63 270 bottom
R113  165E_1%  [RES0402]  55.58 22.63 270 bottom
R114  22E_1%  [RES0402]  38.08 22.56 0 bottom
R115  22E_1%  [RES0402]  43.67 21.72 90 bottom
R116  22E_1%  [RES0402]  50.96 21.01 180 bottom
R117  0E  [RES0402]  55.27 19.16 90 bottom
R118  0E  [RES0402]  55.76 18.67 0 bottom
R119  240E_1%  [RES0402]  19.59 14.48 90 top
R120  4.7K  [RES0402]  70.49 31.93 180 top
R121  10K  [RES0402]  55.62 10.62 180 bottom
R122  49.9E_1%  [RES0402]  40.85 9.32 270 bottom
R123  22E_1%  [RES0402]  52.68 8.97 270 bottom
R124  22E_1%  [RES0402]  49.05 8.89 270 bottom
R125  22E_1%  [RES0402]  47.91 8.89 90 bottom
R126  22E_1%  [RES0402]  44.48 8.76 270 bottom
R127  22E_1%  [RES0402]  43.46 8.76 270 bottom
R128  22E_1%  [RES0402]  42.45 8.76 90 bottom
R129  22E_1%  [RES0402]  50.52 8.71 270 bottom
R130  10K  [RES0402]  56.04 8 180 bottom
R131  10K  [RES0402]  40.8 7.75 180 bottom
R132  240E_1%  [RES0402]  28.45 7.32 90 bottom
R133  22E_1%  [RES0402]  47.71 11.35 270 bottom
R134  22E_1%  [RES0402]  56.04 6.99 180 bottom
R135  22E_1%  [RES0402]  48.67 5.33 90 bottom
R136  22E_1%  [RES0402]  45.11 4.19 270 bottom
R137  0E  [RES0402]  43.84 4.19 270 bottom
R138  0E  [RES0402]  42.57 4.19 90 bottom
R139  22E_1%  [RES0402]  40.03 3.81 270 bottom
R141  100E_0.1%  [RES0402]  27.33 49.28 180 bottom
R142  0E  [RES0402]  55.3 39.57 270 top
RA1  22E  [RESA_741X083_0402-4]  43.06 28.53 180 top
RA2  22E  [RESA_0402-4]  31.53 26.29 90 top
RA3  22E  [RESA_0402-4]  35.08 26.29 90 top
RA4  51E  [RESA_YC124_0402-4]  19.23 19.15 270 top
RA5  22E  [RESA_741X083_0402-4]  64.56 57.57 270 bottom
RA6  51E  [RESA_YC124_0402-4]  26.19 24.89 0 bottom
RA7  51E  [RESA_YC124_0402-4]  20.48 20.78 90 bottom
RA8  51E  [RESA_YC124_0402-4]  23.52 24.89 0 bottom
RA9  22E  [RESA_741X083_0402-4]  43.87 24.54 0 bottom
RA10  51E  [RESA_YC124_0402-4]  25.07 20.12 90 bottom
RA11  51E  [RESA_YC124_0402-4]  19.21 17.02 90 bottom
RA12  22E  [RESA_741X083_0402-4]  46.94 5.06 180 bottom
RA13  22E  [RESA_741X083_0402-4]  53.24 4.85 90 bottom
SW1  CHS-01TA  [SW2_CHS-01TA_SMD]  37.49 36.86 0 top
TP1  SMD  [TP40_SMD]  37.37 60.58 0 top
TP2  SMD  [TP40_SMD]  42.19 59.56 270 top
TP3  SMD  [TP40_SMD]  15.65 58.9 0 top
TP4  SMD  [TP40_SMD]  10.24 58.5 0 top
TP5  SMD  [TP40_SMD]  48.38 55.23 90 top
TP6  SMD  [TP40_SMD]  50.44 55.19 90 top
TP7  SMD  [TP40_SMD]  42.32 54.1 0 top
TP8  SMD  [TP40_SMD]  43.97 50.17 0 top
TP9  SMD  [TP40_SMD]  45.5 48.77 90 top
TP10  SMD  [TP40_SMD]  43.84 47.63 90 top
TP11  SMD  [TP40_SMD]  24.41 46.23 0 top
TP12  SMD  [TP40_SMD]  40.26 44.2 0 top
TP13  SMD  [TP40_SMD]  11.36 38.61 0 top
TP14  SMD  [TP40_SMD]  12.48 19.43 0 top
TP15  SMD  [TP40_SMD]  68.03 11.05 0 top
U1  TPS6591133A2ZRCR  [BGA98_25-59_360X240]  34 50.35 90 top
U2  SN74AVC4T245RGYR  [QFN16_19-68_160X140]  51.53 44.25 270 top
U3  TXS0108ERGYR  [QFN20_19-68_185X145]  61.95 42.89 90 top
U4  SN74CBTLV3257RGYR  [QFN16_19-68_160X140]  51.56 38.09 90 top
U5  SN74AVC4T245RGYR  [QFN16_19-68_160X140]  61.76 34.69 90 top
U6  MT41K256M16TW  [FBGA96_31-49_560X320]  28.31 19.75 270 top
U7  DM388AAAR21FP  [BGA609_19-68_635X635]  47.98 16.84 270 top
U8  MT41K256M16TW  [FBGA96_31-49_560X320]  28.31 9.59 270 top
U9  TPS71711DCKR  [SC70-5]  67.74 8.46 90 top
U10  32.768 KHz  [OSC4_TC25M5I32_110X90_SMD]  39.02 3.3 90 top
U11  SN74LVC1G11DCKR  [SC70-6]  42.07 3.18 90 top
U12  SN74AVC4T245RGYR  [QFN16_19-68_160X140]  44.49 57.62 180 bottom
U13  MT29F2G16ABAEAWP:E  [TSOP48_19-68_730X480]  47.25 39.21 180 bottom
U14  TPS51216RUKR  [QFN20_15-74_120X120]  25.8 32.32 90 bottom
Y1  32.768KHz  [XTAL_9HT10_130X60_SMD]  33.61 57.61 180 top
Y2  20MHz  [XTAL4_ECS_130X100_SMD]  57.69 5.84 180 top
Y3  27.000MHZ  [XTAL4_FA-238V_130X105_SMD]  47.53 2.99 180 top

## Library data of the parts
A1 A2 = ANT_431115300245
C1-C11 C13-C42 C44-C190 = CAP
C12 C43 = CAP_POL
D1 = TLV431AQDBVR_SOT23-5
J1 J2 = CON_3_U.FL-R-SMT
J3 = CON_PMC40X2_FX11LA_M
J4 = CON_PMC_FX11LA-80S
J5 = CON_PMC30X2_FX11LA_M
L1-L8 = INDUCTOR
LD1 = DIODE_LED
MOD1 = MODULE_WL1837
Q1-Q4 = MOSFET_CSD17313Q2
R1-R6 R8 R17 R21 R27 R36 R37 R71 R75 R104 R109-R111 R137 R138 R142 = RESISTOR: signal model: RESISTOR_RES0402_0E_0E
R7 R9-R14 R16 R18-R20 R22-R26 R28-R35 R38-R70 R72 R74 R76-R103 R105 R107 R108 R112 R113 R115 R116 R119-R136 R139 R141 = RESISTOR
R15 R117 R118 = R
R73 R106 R114 = RESISTOR: signal model: RESISTOR_RES0402_22E_1%_22E_1%
RA1 RA5 RA9 RA12 RA13 = RESARR_ISO4
RA2 RA3 = RESARR_ISO4: signal model: RESARR_ISO4_RESA_0402-4_22E_22E
RA4 RA6-RA8 RA10 RA11 = RESARR_ISO4: signal model: RESARR_ISO4_RESA_YC124_0402-4_5_51E
SW1 = SW2_CHS-01TA
TP1-TP15 = TESTPOINT
U1 = TPS659113A2_BGA98
U2 U5 U12 = SN74AVC4T245RGYR_QFN16
U3 = TXS0108ERGYR_QFN20
U4 = SN74CBTLV3257RGYR_QFN16: signal model: SN74CBTLV3257RGYR_QFN16_QFN16_1_SN74CBTLV3257RGYR
U6 U8 = MT41K256M16HA_FBGA96
U7 = DM385AAAR21F_BGA609
U9 = TPS71711DCKR_SC70-5
U10 = OSC_TC25M5I32K7680
U11 = SN74LVC1G11DCKR_SC70-6
U13 = MT29F2G16ABAEAWP_TSOP48
U14 = TPS51216RUKR_QFN20
Y1 = CRY
Y2 Y3 = CRY4_13

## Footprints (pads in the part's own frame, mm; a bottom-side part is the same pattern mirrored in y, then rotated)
ANT2_W3006_390X130_SMD
  rect 1.702x3.15 smd: 1(-4.55,0) 2(4.55,0)
BGA98_25-59_360X240
  round 0.33 smd: A1(-2.275,3.9) A2(-1.625,3.9) A3(-0.975,3.9) A4(-0.325,3.9) A5(0.325,3.9) A6(0.975,3.9) A7(1.625,3.9) A8(2.275,3.9) B1(-2.275,3.25) B2(-1.625,3.25) B3(-0.975,3.25) B4(-0.325,3.25) B5(0.325,3.25) B6(0.975,3.25) B7(1.625,3.25) B8(2.275,3.25) C1(-2.275,2.6) C2(-1.625,2.6) C4(-0.325,2.6) C5(0.325,2.6) C6(0.975,2.6) C7(1.625,2.6) C8(2.275,2.6) D1(-2.275,1.95) D2(-1.625,1.95) D3(-0.975,1.95) D4(-0.325,1.95) D5(0.325,1.95) D6(0.975,1.95) D7(1.625,1.95) D8(2.275,1.95) E1(-2.275,1.3) E2(-1.625,1.3) E4(-0.325,1.3) E5(0.325,1.3) E6(0.975,1.3) E7(1.625,1.3) E8(2.275,1.3) F1(-2.275,0.65) F2(-1.625,0.65) F3(-0.975,0.65) F4(-0.325,0.65) F5(0.325,0.65) F6(0.975,0.65) F7(1.625,0.65) F8(2.275,0.65) G1(-2.275,0) G2(-1.625,0) G3(-0.975,0) G4(-0.325,0) G6(0.975,0) G7(1.625,0) G8(2.275,0) H1(-2.275,-0.65) H2(-1.625,-0.65) H4(-0.325,-0.65) H5(0.325,-0.65) H6(0.975,-0.65) H7(1.625,-0.65) H8(2.275,-0.65) J1(-2.275,-1.3) J2(-1.625,-1.3) J3(-0.975,-1.3) J4(-0.325,-1.3) J5(0.325,-1.3) J6(0.975,-1.3) J7(1.625,-1.3) J8(2.275,-1.3) K1(-2.275,-1.95) K2(-1.625,-1.95) K3(-0.975,-1.95) K5(0.325,-1.95) K7(1.625,-1.95) K8(2.275,-1.95) L1(-2.275,-2.6) L2(-1.625,-2.6) L3(-0.975,-2.6) L4(-0.325,-2.6) L5(0.325,-2.6) L6(0.975,-2.6) L7(1.625,-2.6) L8(2.275,-2.6) M1(-2.275,-3.25) M2(-1.625,-3.25) M3(-0.975,-3.25) M4(-0.325,-3.25) M5(0.325,-3.25) M6(0.975,-3.25) M7(1.625,-3.25) M8(2.275,-3.25) N1(-2.275,-3.9) N2(-1.625,-3.9) N3(-0.975,-3.9) N4(-0.325,-3.9) N5(0.325,-3.9) N6(0.975,-3.9) N7(1.625,-3.9) N8(2.275,-3.9)
BGA609_19-68_635X635
  round 0.254 smd: A1(-7.5,7.5) A2(-7,7.5) A3(-6.5,7.5) A5(-5.5,7.5) A6(-5,7.5) A8(-4,7.5) A9(-3.5,7.5) A11(-2.5,7.5) A12(-2,7.5) A14(-1,7.5) A15(-0.5,7.5) A17(0.5,7.5) A18(1,7.5) A20(2,7.5) A21(2.5,7.5) A23(3.5,7.5) A24(4,7.5) A26(5,7.5) A27(5.5,7.5) A29(6.5,7.5) A30(7,7.5) A31(7.5,7.5) AA1(-7.5,-2.5) AA2(-7,-2.5) AA10(-3,-2.5) AA12(-2,-2.5) AA13(-1.5,-2.5) AA14(-1,-2.5) AA15(-0.5,-2.5) AA16(0,-2.5) AA17(0.5,-2.5) AA18(1,-2.5) AA19(1.5,-2.5) AA20(2,-2.5) AA26(5,-2.5) AA27(5.5,-2.5) AA28(6,-2.5) AA29(6.5,-2.5) AA30(7,-2.5) AB1(-7.5,-3) AB2(-7,-3) AB9(-3.5,-3) AB10(-3,-3) AB12(-2,-3) AB14(-1,-3) AB15(-0.5,-3) AB17(0.5,-3) AB18(1,-3) AB21(2.5,-3) AB22(3,-3) AB30(7,-3) AB31(7.5,-3) AC2(-7,-3.5) AC3(-6.5,-3.5) AC4(-6,-3.5) AC5(-5.5,-3.5) AC6(-5,-3.5) AC7(-4.5,-3.5) AC8(-4,-3.5) AC9(-3.5,-3.5) AC13(-1.5,-3.5) AC15(-0.5,-3.5) AC16(0,-3.5) AC17(0.5,-3.5) AC18(1,-3.5) AC19(1.5,-3.5) AC22(3,-3.5) AC23(3.5,-3.5) AC24(4,-3.5) AC25(4.5,-3.5) AC30(7,-3.5) AC31(7.5,-3.5) AD1(-7.5,-4) AD2(-7,-4) AD3(-6.5,-4) AD4(-6,-4) AD5(-5.5,-4) AD6(-5,-4) AD7(-4.5,-4) AD8(-4,-4) AD9(-3.5,-4) AD12(-2,-4) AD15(-0.5,-4) AD16(0,-4) AD19(1.5,-4) AD20(2,-4) AD23(3.5,-4) AD24(4,-4) AD25(4.5,-4) AD26(5,-4) AD27(5.5,-4) AD28(6,-4) AD29(6.5,-4) AD30(7,-4) AE1(-7.5,-4.5) AE2(-7,-4.5) AE3(-6.5,-4.5) AE4(-6,-4.5) AE5(-5.5,-4.5) AE6(-5,-4.5) AE7(-4.5,-4.5) AE8(-4,-4.5) AE9(-3.5,-4.5) AE12(-2,-4.5) AE15(-0.5,-4.5) AE16(0,-4.5) AE19(1.5,-4.5) AE20(2,-4.5) AE23(3.5,-4.5) AE24(4,-4.5) AE25(4.5,-4.5) AE26(5,-4.5) AE27(5.5,-4.5) AE28(6,-4.5) AE29(6.5,-4.5) AE30(7,-4.5) AE31(7.5,-4.5) AF2(-7,-5) AF7(-4.5,-5) AF8(-4,-5) AF11(-2.5,-5) AF12(-2,-5) AF15(-0.5,-5) AF16(0,-5) AF19(1.5,-5) AF20(2,-5) AF23(3.5,-5) AF24(4,-5) AF25(4.5,-5) AF27(5.5,-5) AF29(6.5,-5) AF30(7,-5) AF31(7.5,-5) AG1(-7.5,-5.5) AG2(-7,-5.5) AG3(-6.5,-5.5) AG4(-6,-5.5) AG6(-5,-5.5) AG7(-4.5,-5.5) AG8(-4,-5.5) AG11(-2.5,-5.5) AG12(-2,-5.5) AG15(-0.5,-5.5) AG16(0,-5.5) AG19(1.5,-5.5) AG20(2,-5.5) AG23(3.5,-5.5) AG24(4,-5.5) AG25(4.5,-5.5) AG30(7,-5.5) AH1(-7.5,-6) AH2(-7,-6) AH7(-4.5,-6) AH8(-4,-6) AH11(-2.5,-6) AH12(-2,-6) AH15(-0.5,-6) AH16(0,-6) AH19(1.5,-6) AH20(2,-6) AH23(3.5,-6) AH24(4,-6) AH25(4.5,-6) AH27(5.5,-6) AH29(6.5,-6) AH30(7,-6) AH31(7.5,-6) AJ2(-7,-6.5) AJ4(-6,-6.5) AJ6(-5,-6.5) AJ7(-4.5,-6.5) AJ8(-4,-6.5) AJ11(-2.5,-6.5) AJ12(-2,-6.5) AJ15(-0.5,-6.5) AJ16(0,-6.5) AJ19(1.5,-6.5) AJ20(2,-6.5) AJ23(3.5,-6.5) AJ24(4,-6.5) AJ25(4.5,-6.5) AJ27(5.5,-6.5) AJ30(7,-6.5) AJ31(7.5,-6.5) AK1(-7.5,-7) AK2(-7,-7) AK3(-6.5,-7) AK4(-6,-7) AK5(-5.5,-7) AK6(-5,-7) AK7(-4.5,-7) AK8(-4,-7) AK9(-3.5,-7) AK10(-3,-7) AK11(-2.5,-7) AK12(-2,-7) AK13(-1.5,-7) AK14(-1,-7) AK15(-0.5,-7) AK16(0,-7) AK17(0.5,-7) AK18(1,-7) AK19(1.5,-7) AK20(2,-7) AK21(2.5,-7) AK22(3,-7) AK23(3.5,-7) AK24(4,-7) AK25(4.5,-7) AK26(5,-7) AK27(5.5,-7) AK28(6,-7) AK29(6.5,-7) AK30(7,-7) AL1(-7.5,-7.5) AL2(-7,-7.5) AL3(-6.5,-7.5) AL5(-5.5,-7.5) AL6(-5,-7.5) AL8(-4,-7.5) AL9(-3.5,-7.5) AL11(-2.5,-7.5) AL12(-2,-7.5) AL14(-1,-7.5) AL15(-0.5,-7.5) AL17(0.5,-7.5) AL18(1,-7.5) AL20(2,-7.5) AL21(2.5,-7.5) AL23(3.5,-7.5) AL24(4,-7.5) AL26(5,-7.5) AL27(5.5,-7.5) AL29(6.5,-7.5) AL30(7,-7.5) AL31(7.5,-7.5) B2(-7,7) B3(-6.5,7) B4(-6,7) B5(-5.5,7) B6(-5,7) B7(-4.5,7) B8(-4,7) B9(-3.5,7) B10(-3,7) B11(-2.5,7) B12(-2,7) B13(-1.5,7) B14(-1,7) B15(-0.5,7) B16(0,7) B17(0.5,7) B18(1,7) B19(1.5,7) B20(2,7) B21(2.5,7) B22(3,7) B23(3.5,7) B24(4,7) B25(4.5,7) B26(5,7) B27(5.5,7) B28(6,7) B29(6.5,7) B30(7,7) B31(7.5,7) C1(-7.5,6.5) C2(-7,6.5) C5(-5.5,6.5) C7(-4.5,6.5) C8(-4,6.5) C9(-3.5,6.5) C12(-2,6.5) C13(-1.5,6.5) C16(0,6.5) C17(0.5,6.5) C20(2,6.5) C21(2.5,6.5) C24(4,6.5) C25(4.5,6.5) C26(5,6.5) C28(6,6.5) C30(7,6.5) D1(-7.5,6) D2(-7,6) D3(-6.5,6) D5(-5.5,6) D7(-4.5,6) D8(-4,6) D9(-3.5,6) D12(-2,6) D13(-1.5,6) D16(0,6) D17(0.5,6) D20(2,6) D21(2.5,6) D24(4,6) D25(4.5,6) D30(7,6) D31(7.5,6) E2(-7,5.5) E7(-4.5,5.5) E8(-4,5.5) E9(-3.5,5.5) E12(-2,5.5) E13(-1.5,5.5) E16(0,5.5) E17(0.5,5.5) E20(2,5.5) E21(2.5,5.5) E24(4,5.5) E25(4.5,5.5) E26(5,5.5) E28(6,5.5) E29(6.5,5.5) E30(7,5.5) E31(7.5,5.5) F1(-7.5,5) F2(-7,5) F3(-6.5,5) F5(-5.5,5) F7(-4.5,5) F8(-4,5) F9(-3.5,5) F12(-2,5) F13(-1.5,5) F16(0,5) F17(0.5,5) F20(2,5) F21(2.5,5) F24(4,5) F25(4.5,5) F30(7,5) G1(-7.5,4.5) G2(-7,4.5) G3(-6.5,4.5) G4(-6,4.5) G5(-5.5,4.5) G6(-5,4.5) G7(-4.5,4.5) G8(-4,4.5) G9(-3.5,4.5) G12(-2,4.5) G13(-1.5,4.5) G16(0,4.5) G17(0.5,4.5) G20(2,4.5) G23(3.5,4.5) G24(4,4.5) G25(4.5,4.5) G26(5,4.5) G27(5.5,4.5) G28(6,4.5) G29(6.5,4.5) G30(7,4.5) G31(7.5,4.5) H2(-7,4) H3(-6.5,4) H4(-6,4) H5(-5.5,4) H6(-5,4) H7(-4.5,4) H8(-4,4) H9(-3.5,4) H12(-2,4) H13(-1.5,4) H16(0,4) H17(0.5,4) H20(2,4) H23(3.5,4) H24(4,4) H25(4.5,4) H26(5,4) H27(5.5,4) H28(6,4) H29(6.5,4) H30(7,4) H31(7.5,4) J1(-7.5,3.5) J2(-7,3.5) J7(-4.5,3.5) J8(-4,3.5) J9(-3.5,3.5) J10(-3,3.5) J13(-1.5,3.5) J14(-1,3.5) J16(0,3.5) J17(0.5,3.5) J19(1.5,3.5) J23(3.5,3.5) J24(4,3.5) J25(4.5,3.5) J26(5,3.5) J27(5.5,3.5) J28(6,3.5) J29(6.5,3.5) J30(7,3.5) K1(-7.5,3) K2(-7,3) K10(-3,3) K11(-2.5,3) K14(-1,3) K16(0,3) K17(0.5,3) K19(1.5,3) K20(2,3) K22(3,3) K23(3.5,3) K30(7,3) K31(7.5,3) L2(-7,2.5) L3(-6.5,2.5) L4(-6,2.5) L5(-5.5,2.5) L6(-5,2.5) L12(-2,2.5) L13(-1.5,2.5) L14(-1,2.5) L15(-0.5,2.5) L16(0,2.5) L17(0.5,2.5) L18(1,2.5) L19(1.5,2.5) L20(2,2.5) L22(3,2.5) L30(7,2.5) L31(7.5,2.5) M1(-7.5,2) M2(-7,2) M3(-6.5,2) M4(-6,2) M5(-5.5,2) M6(-5,2) M7(-4.5,2) M8(-4,2) M10(-3,2) M11(-2.5,2) M13(-1.5,2) M14(-1,2) M16(0,2) M17(0.5,2) M19(1.5,2) M20(2,2) M21(2.5,2) M24(4,2) M25(4.5,2) M26(5,2) M27(5.5,2) M28(6,2) M29(6.5,2) M30(7,2) N1(-7.5,1.5) N2(-7,1.5) N9(-3.5,1.5) N10(-3,1.5) N11(-2.5,1.5) N13(-1.5,1.5) N14(-1,1.5) N16(0,1.5) N17(0.5,1.5) N19(1.5,1.5) N20(2,1.5) N22(3,1.5) N23(3.5,1.5) N24(4,1.5) N25(4.5,1.5) N26(5,1.5) N27(5.5,1.5) N28(6,1.5) N29(6.5,1.5) N30(7,1.5) N31(7.5,1.5) P2(-7,1) P11(-2.5,1) P12(-2,1) P14(-1,1) P15(-0.5,1) P17(0.5,1) P18(1,1) P20(2,1) P21(2.5,1) P23(3.5,1) P30(7,1) P31(7.5,1) R1(-7.5,0.5) R2(-7,0.5) R3(-6.5,0.5) R4(-6,0.5) R5(-5.5,0.5) R6(-5,0.5) R7(-4.5,0.5) R8(-4,0.5) R9(-3.5,0.5) R11(-2.5,0.5) R12(-2,0.5) R14(-1,0.5) R15(-0.5,0.5) R17(0.5,0.5) R18(1,0.5) R20(2,0.5) R21(2.5,0.5) R30(7,0.5) T1(-7.5,0) T2(-7,0) T3(-6.5,0) T4(-6,0) T5(-5.5,0) T6(-5,0) T7(-4.5,0) T8(-4,0) T9(-3.5,0) T10(-3,0) T11(-2.5,0) T12(-2,0) T13(-1.5,0) T14(-1,0) T15(-0.5,0) T16(0,0) T17(0.5,0) T18(1,0) T19(1.5,0) T20(2,0) T21(2.5,0) T22(3,0) T23(3.5,0) T24(4,0) T25(4.5,0) T26(5,0) T27(5.5,0) T28(6,0) T29(6.5,0) T30(7,0) T31(7.5,0) U2(-7,-0.5) U9(-3.5,-0.5) U11(-2.5,-0.5) U12(-2,-0.5) U14(-1,-0.5) U15(-0.5,-0.5) U17(0.5,-0.5) U18(1,-0.5) U20(2,-0.5) U21(2.5,-0.5) U23(3.5,-0.5) U24(4,-0.5) U25(4.5,-0.5) U26(5,-0.5) U27(5.5,-0.5) U28(6,-0.5) U29(6.5,-0.5) U30(7,-0.5) U31(7.5,-0.5) V1(-7.5,-1) V2(-7,-1) V9(-3.5,-1) V11(-2.5,-1) V12(-2,-1) V14(-1,-1) V15(-0.5,-1) V17(0.5,-1) V18(1,-1) V20(2,-1) V21(2.5,-1) V30(7,-1) W1(-7.5,-1.5) W2(-7,-1.5) W3(-6.5,-1.5) W4(-6,-1.5) W5(-5.5,-1.5) W6(-5,-1.5) W7(-4.5,-1.5) W8(-4,-1.5) W9(-3.5,-1.5) W10(-3,-1.5) W11(-2.5,-1.5) W13(-1.5,-1.5) W14(-1,-1.5) W16(0,-1.5) W17(0.5,-1.5) W19(1.5,-1.5) W20(2,-1.5) W22(3,-1.5) W23(3.5,-1.5) W30(7,-1.5) W31(7.5,-1.5) Y2(-7,-2) Y3(-6.5,-2) Y4(-6,-2) Y5(-5.5,-2) Y6(-5,-2) Y7(-4.5,-2) Y8(-4,-2) Y11(-2.5,-2) Y13(-1.5,-2) Y14(-1,-2) Y16(0,-2) Y17(0.5,-2) Y19(1.5,-2) Y20(2,-2) Y21(2.5,-2) Y22(3,-2) Y24(4,-2) Y25(4.5,-2) Y26(5,-2) Y27(5.5,-2) Y28(6,-2) Y29(6.5,-2) Y30(7,-2) Y31(7.5,-2)
CAP0201
  rect 0.356x0.33 smd: 1(-0.28,0) 2(0.28,0)
CAP0402
  rect 0.559x0.635 smd: 1(-0.49,0) 2(0.49,0)
CAP0603
  rect 0.94x1.016 smd: 1(-0.8,0) 2(0.8,0)
CAPT7343D
  rect 2.362x2.438 smd: 1(-3.1,0) 2(3.1,0)
CAPT7343X
  rect 2.362x2.438 smd: 1(-3.1,0) 2(3.1,0)
CON_3X1_U-FL-R-SMT_S_S_S
  rect 1.118x1.067 smd: 1(1.525,0)
  rect 2.261x1.067 smd: 2(0,1.475) 3(0,-1.475)
CON_PMC30X2_FX11LA-60P_P_S_S
  rect 1.6x1.905 smd: (-10.5,0) (10.5,0)
  round 0.787 hole 0.914 unplated: (-9,0)
  round 0.889 hole 1.016 unplated: (9,0)
  rect 0.33x0.889 smd: 1(-8.75,-2.375) 2(-8.75,2.375) 3(-8.25,-2.375) 4(-8.25,2.375) 5(-7.75,-2.375) 6(-7.75,2.375) 7(-7.25,-2.375) 8(-7.25,2.375) 9(-6.75,-2.375) 10(-6.75,2.375) 13(-5.25,-2.375) 14(-5.25,2.375) 15(-4.75,-2.375) 16(-4.75,2.375) 17(-4.25,-2.375) 18(-4.25,2.375) 19(-3.75,-2.375) 20(-3.75,2.375) 21(-3.25,-2.375) 22(-3.25,2.375) 23(-2.75,-2.375) 24(-2.75,2.375) 25(-2.25,-2.375) 26(-2.25,2.375) 27(-1.75,-2.375) 28(-1.75,2.375) 29(-1.25,-2.375) 30(-1.25,2.375) 31(-0.75,-2.375) 32(-0.75,2.375) 35(0.75,-2.375) 36(0.75,2.375) 37(1.25,-2.375) 38(1.25,2.375) 39(1.75,-2.375) 40(1.75,2.375) 41(2.25,-2.375) 42(2.25,2.375) 43(2.75,-2.375) 44(2.75,2.375) 45(3.25,-2.375) 46(3.25,2.375) 47(3.75,-2.375) 48(3.75,2.375) 49(4.25,-2.375) 50(4.25,2.375) 51(4.75,-2.375) 52(4.75,2.375) 53(5.25,-2.375) 54(5.25,2.375) 57(6.75,-2.375) 58(6.75,2.375) 59(7.25,-2.375) 60(7.25,2.375) 61(7.75,-2.375) 62(7.75,2.375) 63(8.25,-2.375) 64(8.25,2.375) 65(8.75,-2.375) 66(8.75,2.375)
  rect 0.711x1.321 smd: 11(-6,-2.172) 12(-6,2.172) 33(0,-2.172) 34(0,2.172) 55(6,-2.172) 56(6,2.172)
CON_PMC40X2_FX11LA-80P_P_S_S
  rect 1.6x1.905 smd: (-13.5,0) (13.5,0)
  round 0.838 hole 0.965 unplated: (-12,0)
  round 0.94 hole 1.067 unplated: (12,0)
  rect 0.33x0.914 smd: 1(-11.75,-2.375) 2(-11.75,2.375) 3(-11.25,-2.375) 4(-11.25,2.375) 5(-10.75,-2.375) 6(-10.75,2.375) 7(-10.25,-2.375) 8(-10.25,2.375) 9(-9.75,-2.375) 10(-9.75,2.375) 13(-8.25,-2.375) 14(-8.25,2.375) 15(-7.75,-2.375) 16(-7.75,2.375) 17(-7.25,-2.375) 18(-7.25,2.375) 19(-6.75,-2.375) 20(-6.75,2.375) 21(-6.25,-2.375) 22(-6.25,2.375) 23(-5.75,-2.375) 24(-5.75,2.375) 25(-5.25,-2.375) 26(-5.25,2.375) 27(-4.75,-2.375) 28(-4.75,2.375) 29(-4.25,-2.375) 30(-4.25,2.375) 31(-3.75,-2.375) 32(-3.75,2.375) 35(-2.25,-2.375) 36(-2.25,2.375) 37(-1.75,-2.375) 38(-1.75,2.375) 39(-1.25,-2.375) 40(-1.25,2.375) 41(-0.75,-2.375) 42(-0.75,2.375) 43(-0.25,-2.375) 44(-0.25,2.375) 45(0.25,-2.375) 46(0.25,2.375) 47(0.75,-2.375) 48(0.75,2.375) 49(1.25,-2.375) 50(1.25,2.375) 51(1.75,-2.375) 52(1.75,2.375) 53(2.25,-2.375) 54(2.25,2.375) 57(3.75,-2.375) 58(3.75,2.375) 59(4.25,-2.375) 60(4.25,2.375) 61(4.75,-2.375) 62(4.75,2.375) 63(5.25,-2.375) 64(5.25,2.375) 65(5.75,-2.375) 66(5.75,2.375) 67(6.25,-2.375) 68(6.25,2.375) 69(6.75,-2.375) 70(6.75,2.375) 71(7.25,-2.375) 72(7.25,2.375) 73(7.75,-2.375) 74(7.75,2.375) 75(8.25,-2.375) 76(8.25,2.375) 79(9.75,-2.375) 80(9.75,2.375) 81(10.25,-2.375) 82(10.25,2.375) 83(10.75,-2.375) 84(10.75,2.375) 85(11.25,-2.375) 86(11.25,2.375) 87(11.75,-2.375) 88(11.75,2.375)
  rect 0.737x1.346 smd: 11(-9,-2.15) 12(-9,2.15) 33(-3,-2.15) 34(-3,2.15) 55(3,-2.15) 56(3,2.15) 77(9,-2.15) 78(9,2.15)
CON_PMC40X2_FX11LA-80S_S_S_S
  rect 1.6x1.905 smd: (-14.9,0) (14.9,0)
  round 0.787 hole 0.914 unplated: (-13.4,0)
  round 0.889 hole 1.016 unplated: (13.4,0)
  rect 0.33x0.914 smd: 1(-11.75,2.85) 2(-11.75,-2.85) 3(-11.25,2.85) 4(-11.25,-2.85) 5(-10.75,2.85) 6(-10.75,-2.85) 7(-10.25,2.85) 8(-10.25,-2.85) 9(-9.75,2.85) 10(-9.75,-2.85) 13(-8.25,2.85) 14(-8.25,-2.85) 15(-7.75,2.85) 16(-7.75,-2.85) 17(-7.25,2.85) 18(-7.25,-2.85) 19(-6.75,2.85) 20(-6.75,-2.85) 21(-6.25,2.85) 22(-6.25,-2.85) 23(-5.75,2.85) 24(-5.75,-2.85) 25(-5.25,2.85) 26(-5.25,-2.85) 27(-4.75,2.85) 28(-4.75,-2.85) 29(-4.25,2.85) 30(-4.25,-2.85) 31(-3.75,2.85) 32(-3.75,-2.85) 35(-2.25,2.85) 36(-2.25,-2.85) 37(-1.75,2.85) 38(-1.75,-2.85) 39(-1.25,2.85) 40(-1.25,-2.85) 41(-0.75,2.85) 42(-0.75,-2.85) 43(-0.25,2.85) 44(-0.25,-2.85) 45(0.25,2.85) 46(0.25,-2.85) 47(0.75,2.85) 48(0.75,-2.85) 49(1.25,2.85) 50(1.25,-2.85) 51(1.75,2.85) 52(1.75,-2.85) 53(2.25,2.85) 54(2.25,-2.85) 57(3.75,2.85) 58(3.75,-2.85) 59(4.25,2.85) 60(4.25,-2.85) 61(4.75,2.85) 62(4.75,-2.85) 63(5.25,2.85) 64(5.25,-2.85) 65(5.75,2.85) 66(5.75,-2.85) 67(6.25,2.85) 68(6.25,-2.85) 69(6.75,2.85) 70(6.75,-2.85) 71(7.25,2.85) 72(7.25,-2.85) 73(7.75,2.85) 74(7.75,-2.85) 75(8.25,2.85) 76(8.25,-2.85) 79(9.75,2.85) 80(9.75,-2.85) 81(10.25,2.85) 82(10.25,-2.85) 83(10.75,2.85) 84(10.75,-2.85) 85(11.25,2.85) 86(11.25,-2.85) 87(11.75,2.85) 88(11.75,-2.85)
  rect 0.711x1.321 smd: 11(-9,2.647) 12(-9,-2.647) 33(-3,2.647) 34(-3,-2.647) 55(3,2.647) 56(3,-2.647) 77(9,2.647) 78(9,-2.647)
FBGA96_31-49_560X320
  round 0.406 smd: A1(-3.2,6) A2(-2.4,6) A3(-1.6,6) A7(1.6,6) A8(2.4,6) A9(3.2,6) B1(-3.2,5.2) B2(-2.4,5.2) B3(-1.6,5.2) B7(1.6,5.2) B8(2.4,5.2) B9(3.2,5.2) C1(-3.2,4.4) C2(-2.4,4.4) C3(-1.6,4.4) C7(1.6,4.4) C8(2.4,4.4) C9(3.2,4.4) D1(-3.2,3.6) D2(-2.4,3.6) D3(-1.6,3.6) D7(1.6,3.6) D8(2.4,3.6) D9(3.2,3.6) E1(-3.2,2.8) E2(-2.4,2.8) E3(-1.6,2.8) E7(1.6,2.8) E8(2.4,2.8) E9(3.2,2.8) F1(-3.2,2) F2(-2.4,2) F3(-1.6,2) F7(1.6,2) F8(2.4,2) F9(3.2,2) G1(-3.2,1.2) G2(-2.4,1.2) G3(-1.6,1.2) G7(1.6,1.2) G8(2.4,1.2) G9(3.2,1.2) H1(-3.2,0.4) H2(-2.4,0.4) H3(-1.6,0.4) H7(1.6,0.4) H8(2.4,0.4) H9(3.2,0.4) J1(-3.2,-0.4) J2(-2.4,-0.4) J3(-1.6,-0.4) J7(1.6,-0.4) J8(2.4,-0.4) J9(3.2,-0.4) K1(-3.2,-1.2) K2(-2.4,-1.2) K3(-1.6,-1.2) K7(1.6,-1.2) K8(2.4,-1.2) K9(3.2,-1.2) L1(-3.2,-2) L2(-2.4,-2) L3(-1.6,-2) L7(1.6,-2) L8(2.4,-2) L9(3.2,-2) M1(-3.2,-2.8) M2(-2.4,-2.8) M3(-1.6,-2.8) M7(1.6,-2.8) M8(2.4,-2.8) M9(3.2,-2.8) N1(-3.2,-3.6) N2(-2.4,-3.6) N3(-1.6,-3.6) N7(1.6,-3.6) N8(2.4,-3.6) N9(3.2,-3.6) P1(-3.2,-4.4) P2(-2.4,-4.4) P3(-1.6,-4.4) P7(1.6,-4.4) P8(2.4,-4.4) P9(3.2,-4.4) R1(-3.2,-5.2) R2(-2.4,-5.2) R3(-1.6,-5.2) R7(1.6,-5.2) R8(2.4,-5.2) R9(3.2,-5.2) T1(-3.2,-6) T2(-2.4,-6) T3(-1.6,-6) T7(1.6,-6) T8(2.4,-6) T9(3.2,-6)
IND0402
  rect 0.559x0.635 smd: 1(-0.49,0) 2(0.49,0)
IND_NRS5020_200X200_SMD
  rect 4.013x1.524 smd: 1(0,-1.8) 2(0,1.8)
IND_VLS252012HBX_110X90_SMD
  rect 0.61x2.007 smd: 1(-0.95,0) 2(0.95,0)
IND_XAL4030_170X170_SMD
  rect 0.991x3.708 smd: 1(-1.185,0) 2(1.185,0)
LED_0402
  rect 0.61x0.508 smd: 1(0,-0.45) 2(0,0.45)
MOD100_WL1831M_530X530
  rect 0.762x0.762 smd: 1(-5.975,6.025) 17(-5.975,-6.025) 33(5.975,-6.025) 49(5.975,6.025)
  rect 0.762x0.406 smd: 2(-5.975,4.9) 3(-5.975,4.2) 4(-5.975,3.5) 5(-5.975,2.8) 6(-5.975,2.1) 7(-5.975,1.4) 8(-5.975,0.7) 9(-5.975,0) 10(-5.975,-0.7) 11(-5.975,-1.4) 12(-5.975,-2.1) 13(-5.975,-2.8) 14(-5.975,-3.5) 15(-5.975,-4.2) 16(-5.975,-4.9) 34(5.975,-4.9) 35(5.975,-4.2) 36(5.975,-3.5) 37(5.975,-2.8) 38(5.975,-2.1) 39(5.975,-1.4) 40(5.975,-0.7) 41(5.975,0) 42(5.975,0.7) 43(5.975,1.4) 44(5.975,2.1) 45(5.975,2.8) 46(5.975,3.5) 47(5.975,4.2) 48(5.975,4.9)
  rect 0.406x0.762 smd: 18(-4.9,-6.025) 19(-4.2,-6.025) 20(-3.5,-6.025) 21(-2.8,-6.025) 22(-2.1,-6.025) 23(-1.4,-6.025) 24(-0.7,-6.025) 25(0,-6.025) 26(0.7,-6.025) 27(1.4,-6.025) 28(2.1,-6.025) 29(2.8,-6.025) 30(3.5,-6.025) 31(4.2,-6.025) 32(4.9,-6.025) 50(4.9,6.025) 51(4.2,6.025) 52(3.5,6.025) 53(2.8,6.025) 54(2.1,6.025) 55(1.4,6.025) 56(0.7,6.025) 57(0,6.025) 58(-0.7,6.025) 59(-1.4,6.025) 60(-2.1,6.025) 61(-2.8,6.025) 62(-3.5,6.025) 63(-4.2,6.025) 64(-4.9,6.025)
  rect 1.016x1.016 smd: G1(-3.85,3.85) G2(-3.85,2.45) G3(-3.85,1.05) G4(-3.85,-1.05) G5(-3.85,-2.45) G6(-3.85,-3.85) G7(-2.45,3.85) G8(-2.45,2.45) G9(-2.45,1.05) G10(-2.45,-1.05) G11(-2.45,-2.45) G12(-2.45,-3.85) G13(-1.05,3.85) G14(-1.05,2.45) G15(-1.05,1.05) G16(-1.05,-1.05) G17(-1.05,-2.45) G18(-1.05,-3.85) G19(1.05,3.85) G20(1.05,2.45) G21(1.05,1.05) G22(1.05,-1.05) G23(1.05,-2.45) G24(1.05,-3.85) G25(2.45,3.85) G26(2.45,2.45) G27(2.45,1.05) G28(2.45,-1.05) G29(2.45,-2.45) G30(2.45,-3.85) G31(3.85,3.85) G32(3.85,2.45) G33(3.85,1.05) G34(3.85,-1.05) G35(3.85,-2.45) G36(3.85,-3.85)
OSC4_TC25M5I32_110X90_SMD
  rect 0.991x0.838 smd: 1(-0.85,-0.675) 2(0.85,-0.675) 3(0.85,0.675) 4(-0.85,0.675)
QFN16_19-68_160X140
  rect 0.864x0.279 smd: 1(-1.975,-0.75) 8(1.975,-0.75) 9(1.975,0.75) 16(-1.975,0.75)
  rect 0.279x0.864 smd: 2(-1.25,-1.725) 3(-0.75,-1.725) 4(-0.25,-1.725) 5(0.25,-1.725) 6(0.75,-1.725) 7(1.25,-1.725) 10(1.25,1.725) 11(0.75,1.725) 12(0.25,1.725) 13(-0.25,1.725) 14(-0.75,1.725) 15(-1.25,1.725)
  rect 2.54x2.057 smd: 17(0,0)
QFN20_15-74_120X120
  rect 0.787x0.203 smd: 1(-1.5,0.8) 2(-1.5,0.4) 3(-1.5,0) 4(-1.5,-0.4) 5(-1.5,-0.8) 11(1.5,-0.8) 12(1.5,-0.4) 13(1.5,0) 14(1.5,0.4) 15(1.5,0.8)
  rect 0.203x0.787 smd: 6(-0.8,-1.5) 7(-0.4,-1.5) 8(0,-1.5) 9(0.4,-1.5) 10(0.8,-1.5) 16(0.8,1.5) 17(0.4,1.5) 18(0,1.5) 19(-0.4,1.5) 20(-0.8,1.5)
  rect 1.803x1.803 smd: 21(0,0)
QFN20_19-68_185X145
  rect 0.864x0.279 smd: 1(-2.225,-0.75) 10(2.225,-0.75) 11(2.225,0.75) 20(-2.225,0.75)
  rect 0.279x0.864 smd: 2(-1.75,-1.725) 3(-1.25,-1.725) 4(-0.75,-1.725) 5(-0.25,-1.725) 6(0.25,-1.725) 7(0.75,-1.725) 8(1.25,-1.725) 9(1.75,-1.725) 12(1.75,1.725) 13(1.25,1.725) 14(0.75,1.725) 15(0.25,1.725) 16(-0.25,1.725) 17(-0.75,1.725) 18(-1.25,1.725) 19(-1.75,1.725)
  rect 3.15x2.159 smd: 21(0,0)
RES0402
  rect 0.559x0.635 smd: 1(-0.49,0) 2(0.49,0)
RES0805
  rect 1.194x1.448 smd: 1(-0.95,0) 2(0.95,0)
RESA_0402-4
  rect 0.533x0.508 smd: 1(-0.902,-0.454) 4(0.902,-0.454) 5(0.902,0.454) 8(-0.902,0.454)
  rect 0.254x0.508 smd: 2(-0.254,-0.454) 3(0.254,-0.454) 6(0.254,0.454) 7(-0.254,0.454)
RESA_741X083_0402-4
  rect 0.305x0.508 smd: 1(-0.75,-0.5) 2(-0.25,-0.5) 3(0.25,-0.5) 4(0.75,-0.5) 5(0.75,0.5) 6(0.25,0.5) 7(-0.25,0.5) 8(-0.75,0.5)
RESA_YC124_0402-4
  rect 0.356x0.711 smd: 1(-0.75,-0.575) 2(-0.25,-0.575) 3(0.25,-0.575) 4(0.75,-0.575) 5(0.75,0.575) 6(0.25,0.575) 7(-0.25,0.575) 8(-0.75,0.575)
SC70-5
  rect 0.94x0.406 smd: 1(-1.1,0.65) 2(-1.1,0) 3(-1.1,-0.65) 4(1.1,-0.65) 5(1.1,0.65)
SC70-6
  rect 0.94x0.406 smd: 1(-1.1,0.65) 2(-1.1,0) 3(-1.1,-0.65) 4(1.1,-0.65) 5(1.1,0) 6(1.1,0.65)
SON6_CSD17313Q2_80X80
  rect 0.406x0.457 smd: 1(-0.65,-0.922) 2(0,-0.922) 3(0.65,-0.922) 4(0.65,0.922) 5(0,0.922) 6(-0.65,0.922)
  rect 0.406x0.864 smd: 7(0.65,0.096)
  rect 1.041x1.092 smd: 8(-0.325,0)
SOT23-5
  rect 1.092x0.61 smd: 1(-1.3,0.95) 2(-1.3,0) 3(-1.3,-0.95) 4(1.3,-0.95) 5(1.3,0.95)
SW2_CHS-01TA_SMD
  rect 1.016x1.6 smd: 1(0,-2.54) 2(0,2.54)
TP40_SMD
  round 1.016 smd: 1(0,0)
TSOP48_19-68_730X480
  rect 1.295x0.305 smd: 1(-9.8,5.75) 2(-9.8,5.25) 3(-9.8,4.75) 4(-9.8,4.25) 5(-9.8,3.75) 6(-9.8,3.25) 7(-9.8,2.75) 8(-9.8,2.25) 9(-9.8,1.75) 10(-9.8,1.25) 11(-9.8,0.75) 12(-9.8,0.25) 13(-9.8,-0.25) 14(-9.8,-0.75) 15(-9.8,-1.25) 16(-9.8,-1.75) 17(-9.8,-2.25) 18(-9.8,-2.75) 19(-9.8,-3.25) 20(-9.8,-3.75) 21(-9.8,-4.25) 22(-9.8,-4.75) 23(-9.8,-5.25) 24(-9.8,-5.75) 25(9.8,-5.75) 26(9.8,-5.25) 27(9.8,-4.75) 28(9.8,-4.25) 29(9.8,-3.75) 30(9.8,-3.25) 31(9.8,-2.75) 32(9.8,-2.25) 33(9.8,-1.75) 34(9.8,-1.25) 35(9.8,-0.75) 36(9.8,-0.25) 37(9.8,0.25) 38(9.8,0.75) 39(9.8,1.25) 40(9.8,1.75) 41(9.8,2.25) 42(9.8,2.75) 43(9.8,3.25) 44(9.8,3.75) 45(9.8,4.25) 46(9.8,4.75) 47(9.8,5.25) 48(9.8,5.75)
unnamed#2
  round 0.686 hole 0.813 unplated: (0,0) (1.143,0) (2.286,0)
unnamed#3
  round 2.108 hole 2.235 unplated: (0,0)
XTAL4_ECS_130X100_SMD
  rect 0.889x0.787 smd: 1(-1.05,-0.75) 2(1.05,-0.75) 3(1.05,0.75) 4(-1.05,0.75)
